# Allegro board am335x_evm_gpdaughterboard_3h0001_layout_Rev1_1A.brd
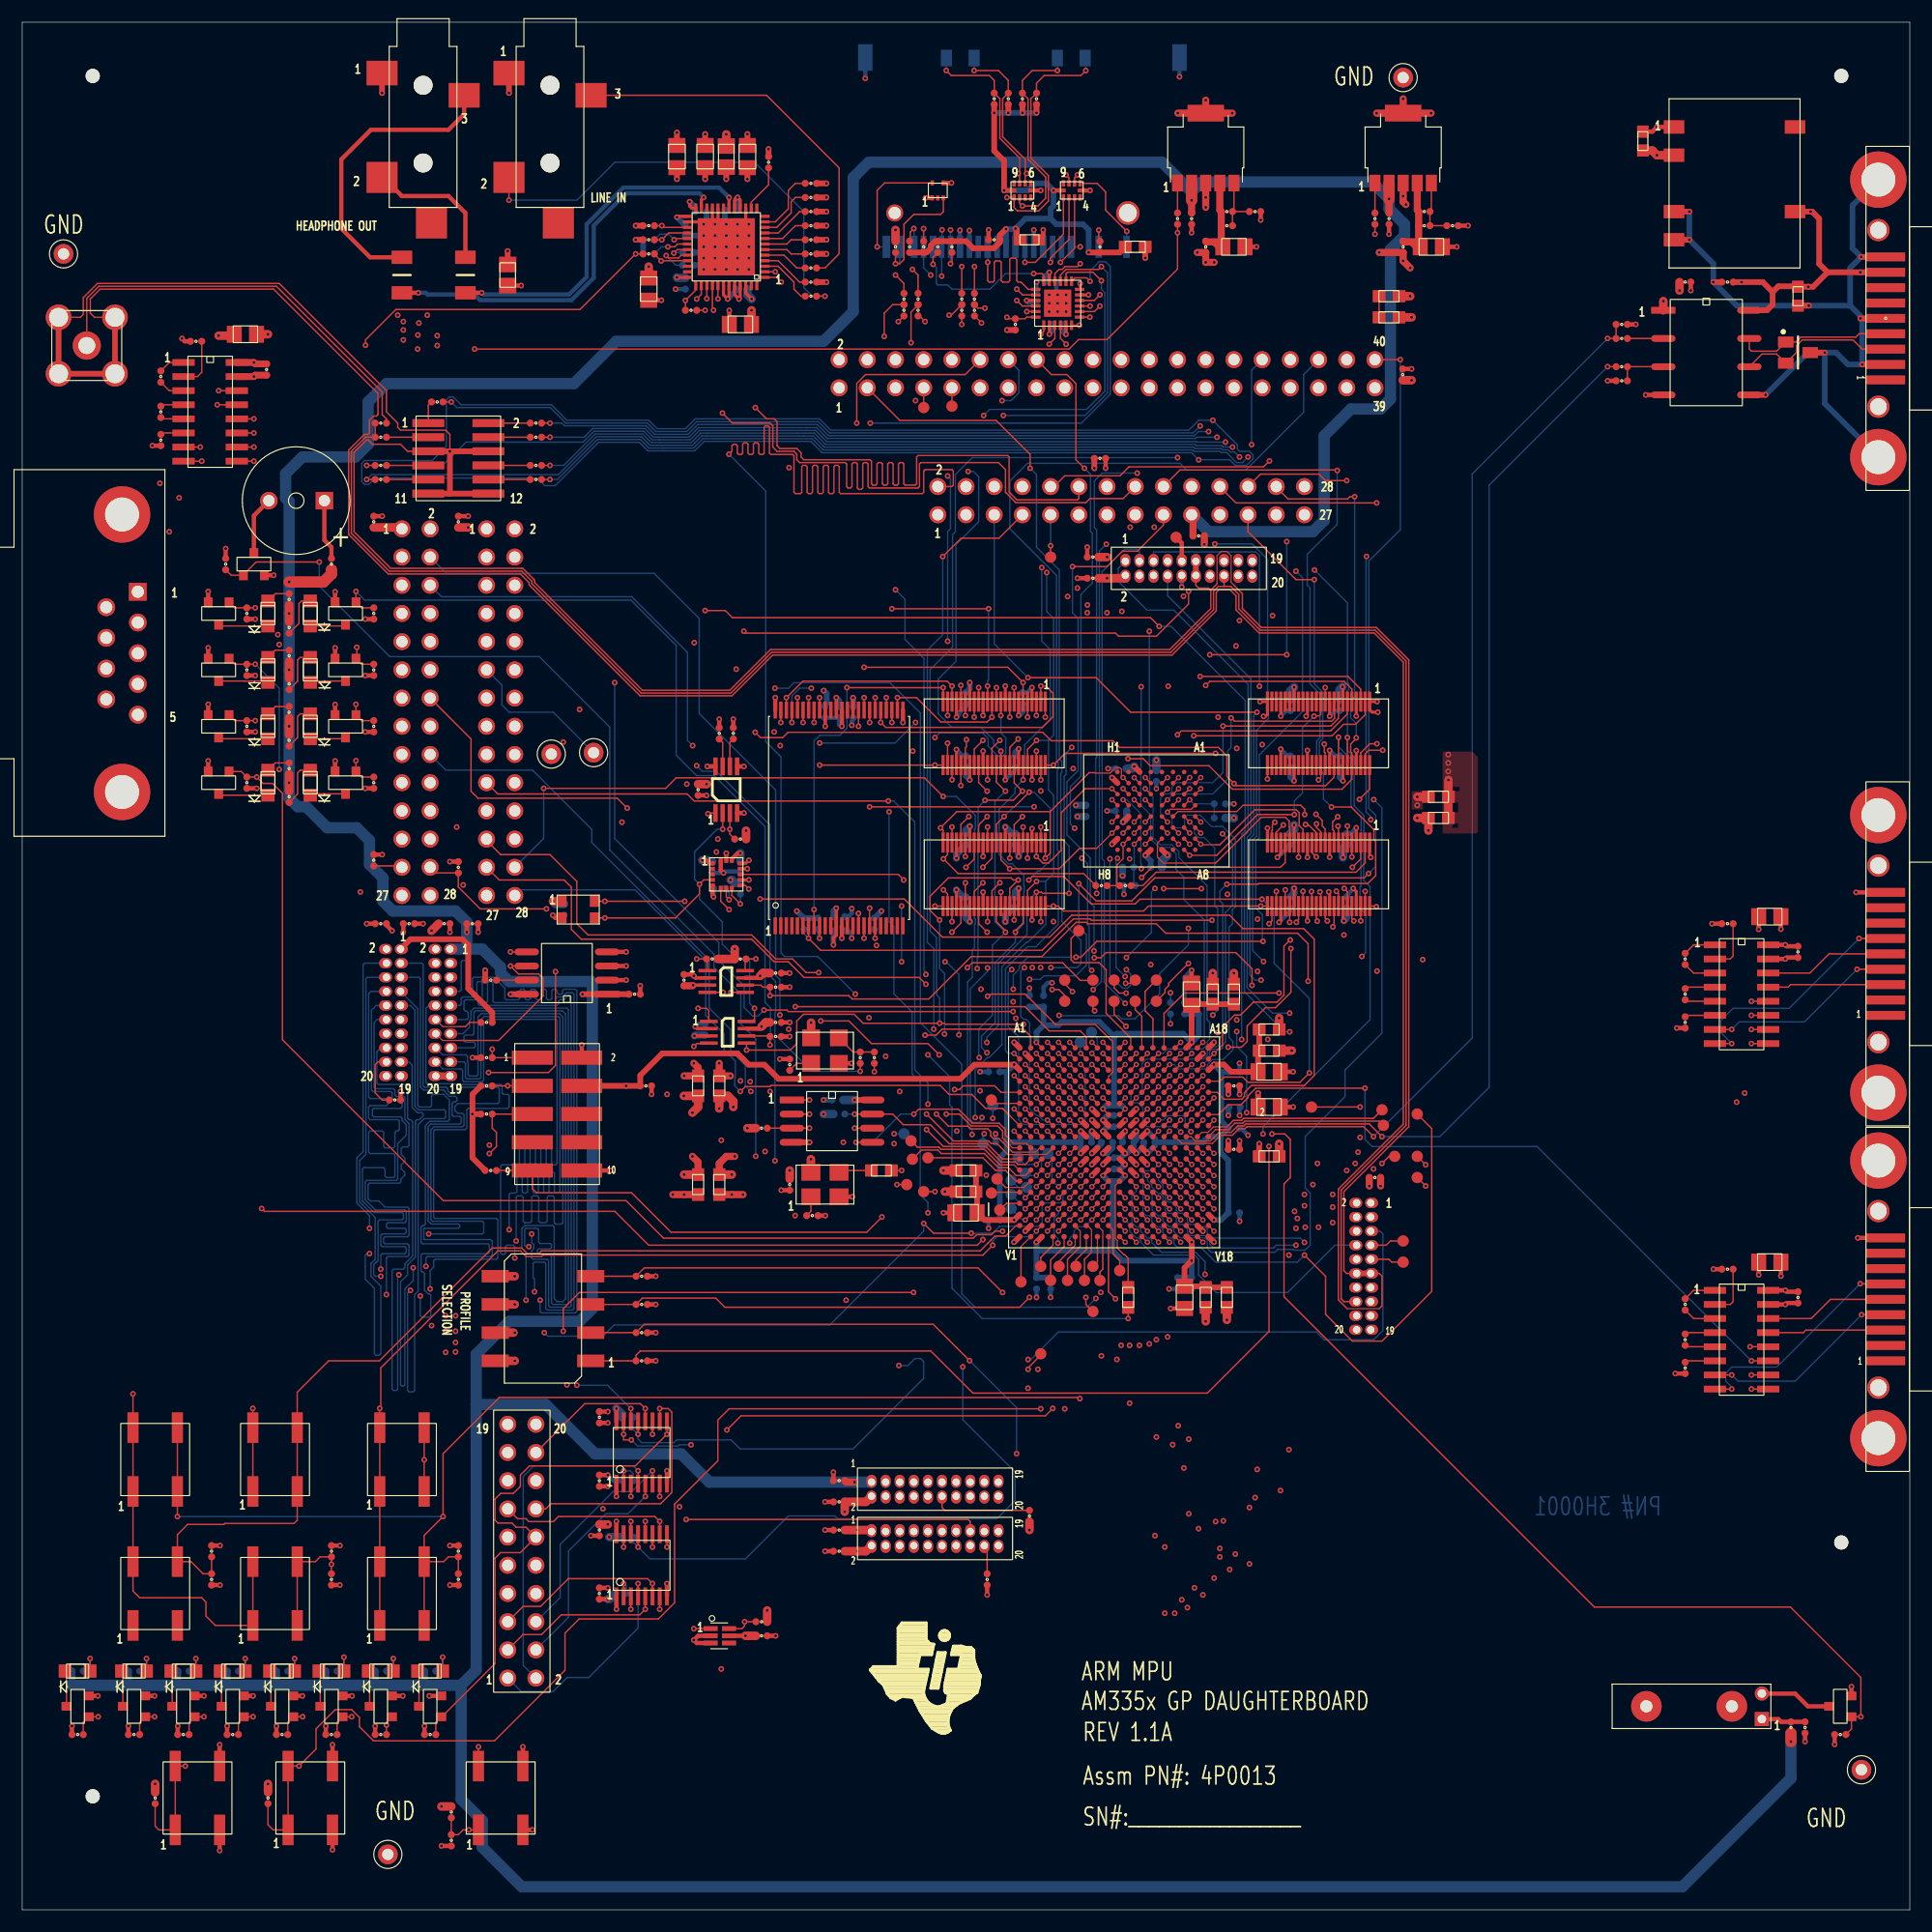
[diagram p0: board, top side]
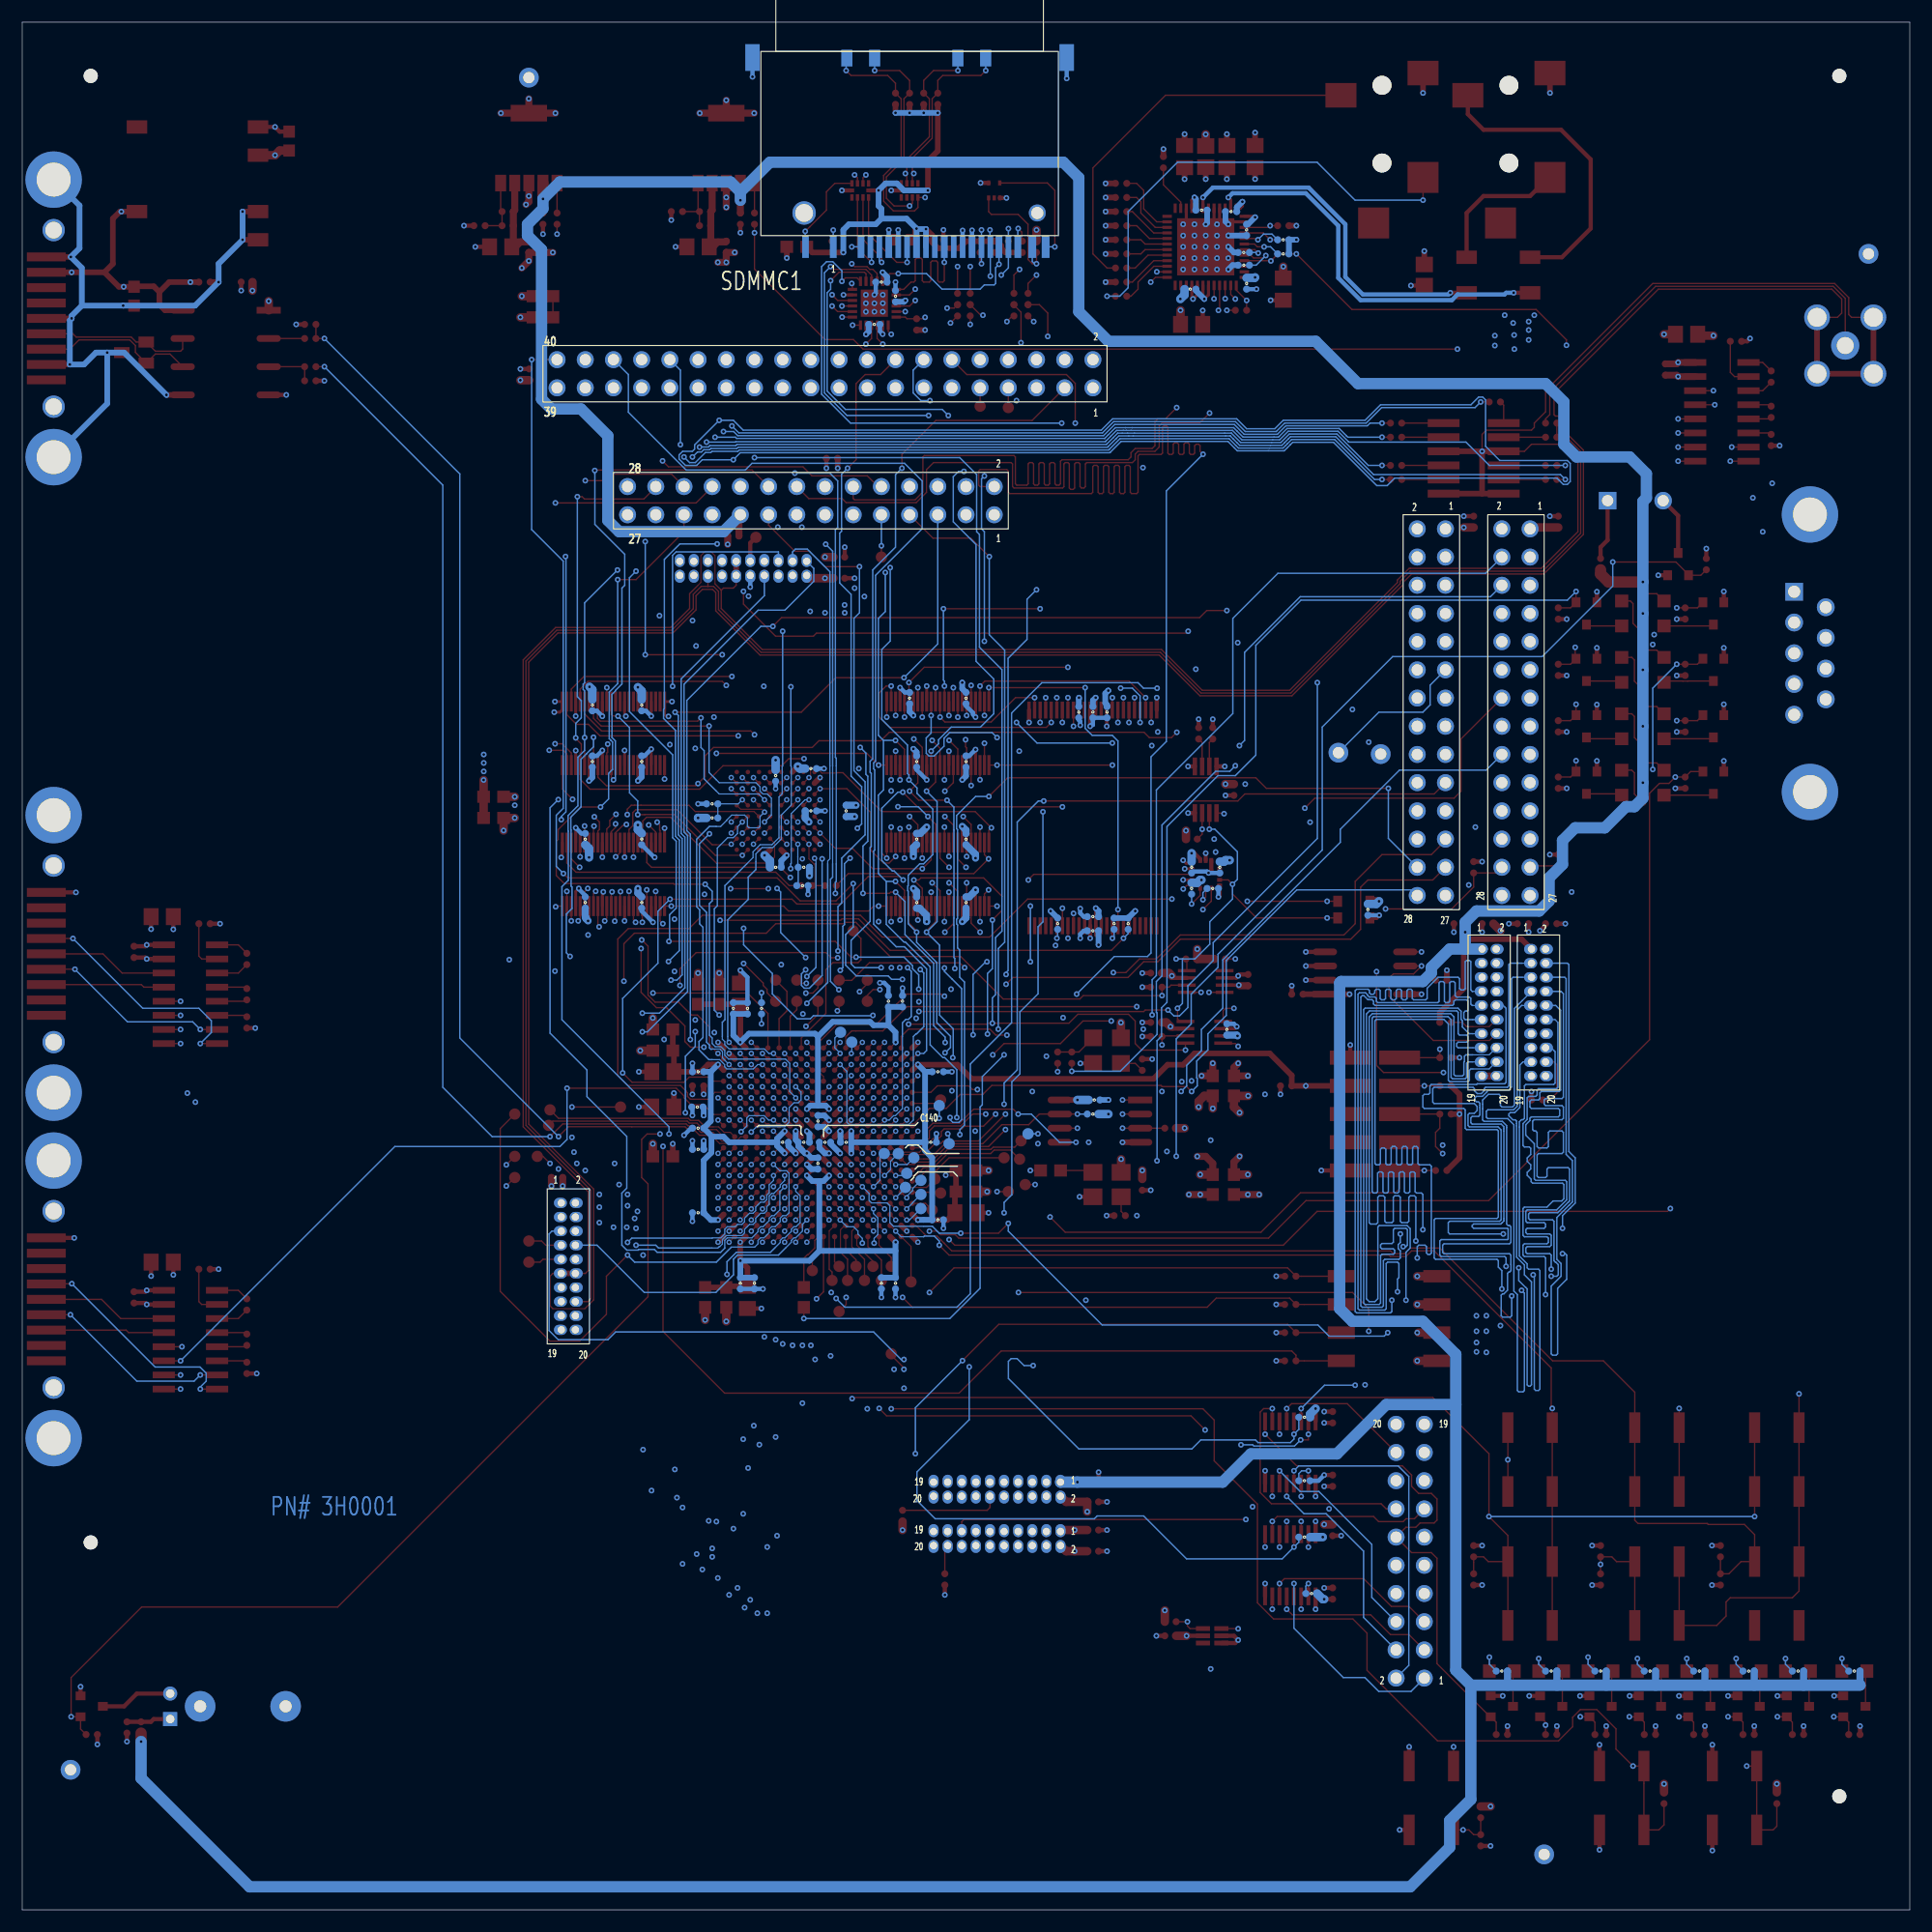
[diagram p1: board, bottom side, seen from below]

Outline 170 x 170 mm; copper layers: TOP, LY2_GND, LY3, LY4_PWR, LY5_PWR, LY6, LY7_GND, BOTTOM. Coordinates in mm from the lower left corner of the outline.
Outline path: 0,170 0,0 170,0 170,170 0,170

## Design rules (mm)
net group GROUP_3: nets AM335X_MDIO_CLK AM335X_MDIO_DATA
net group GROUP_2: nets AM335X_GPMC_A0 AM335X_GPMC_A4 AM335X_GPMC_A5 AM335X_GPMC_A6 AM335X_GPMC_A7 AM335X_GPMC_A8 AM335X_GPMC_A9 AM335X_GPMC_A10 AM335X_GPMC_A11 AM335X_GPMC_WPN
net group GROUP_6: nets AM335X_GPMC_A1 AM335X_GPMC_A2 AM335X_GPMC_A3
net group GROUP_21: nets AM335X_GPMC_AD4 AM335X_GPMC_AD5 AM335X_GPMC_AD6 AM335X_GPMC_AD7
net group GROUP_29: nets MON_AIN0 MON_AIN1 MON_AIN2 MON_AIN3 MON_AIN4 MON_AIN5 MON_AIN6 MON_AIN7 TSC_AIN0 TSC_AIN1 TSC_AIN2 TSC_AIN3 TSC_AIN4 TSC_AIN5 TSC_AIN6 TSC_AIN7
net group GROUP_31: nets GPMC_AD8 GPMC_AD9 GPMC_AD10 GPMC_AD11 GPMC_AD12 GPMC_AD13 GPMC_AD14 GPMC_AD15 LCD_DATA0 LCD_DATA1 LCD_DATA2 LCD_DATA3 LCD_DATA4 LCD_DATA5 LCD_DATA6 LCD_DATA7 LCD_DATA8 LCD_DATA9 LCD_DATA10 LCD_DATA11 LCD_DATA12 LCD_DATA13 LCD_DATA14 LCD_DATA15 LCD_DEN LCD_HSYNC LCD_PCLK LCD_VSYNC LCDBD_D0 LCDBD_D1 LCDBD_D2 LCDBD_D3 LCDBD_D4 LCDBD_D5 LCDBD_D6 LCDBD_D7 LCDBD_D8 LCDBD_D9 LCDBD_D10 LCDBD_D11 LCDBD_D12 LCDBD_D13 LCDBD_D14 LCDBD_D15 LCDBD_D16 LCDBD_D17 LCDBD_D18 LCDBD_D19 LCDBD_D20 LCDBD_D21 LCDBD_D22 LCDBD_D23 LCDBD_DEN LCDBD_HSYNC LCDBD_PCLK LCDBD_VSYNC
net group GROUP_34: nets VCPLD_VIO1 VCPLD_VIO2 VCPLD_VIO3 VCPLD_VIO4
net group GROUP_38: nets AUD_HPLOUT AUD_HPLOUT_JCK AUD_HPROUT AUD_HPROUT_JCK
net group POWER_TRACE: nets VDDSHV5 VGP_1_8D VGP_3_3D
net group SD_MMC_CC: nets SDMMC1_CLK SDMMC1_CMD SDMMC1_DAT0 SDMMC1_DAT1 SDMMC1_DAT2 SDMMC1_DAT3 SDMMC1_DAT4 SDMMC1_DAT5 SDMMC1_DAT6 SDMMC1_DAT7
nets with their own width: min track width 0.381; nets DGND V3_3D VSDMMC1
nets with their own width: min track width 0.508; nets GND_CAN0 VCAN0 VCPLD_INT VDDSHV1 VDDSHV2 VDDSHV3
nets with their own width: min track width 0.635; nets VDDSHV6
nets with their own width: min track width 0.762; nets V1_8D V5_0D

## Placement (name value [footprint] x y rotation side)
C1  0.01uF  [SM-7351-CAP-0402]  55.16 82.46 0 top
C2  0.1uF  [SM-7351-CAP-0402]  39.28 125.01 90 top
C3  0.1uF  [SM-7351-CAP-0402]  31.66 125.01 90 top
C4  0.1uF  [SM-7351-CAP-0402]  96.43 121.83 180 top
C5  0.1uF  [SM-7351-CAP-0402]  124.33 138.27 90 top
C6  0.1uF  [SM-7351-CAP-0402]  105.96 123.74 0 top
C7  0.1uF  [SM-7351-CAP-0402]  97.07 130.72 0 top
C8  0.01uF  [SM-7351-CAP-0402]  34.84 88.81 0 top
C9  0.01uF  [SM-7351-CAP-0402]  32.3 88.81 180 top
C10  0.01uF  [SM-7351-CAP-0402]  38.01 88.81 0 top
C11  0.01uF  [SM-7351-CAP-0402]  40.55 88.81 0 top
C12  0.01uF  [SM-7351-CAP-0402]  121.83 65.95 0 top
C13  0.01uF  [SM-7351-CAP-0402]  114.21 90.72 270 bottom
C14  0.01uF  [SM-7351-CAP-0402]  119.29 90.72 90 bottom
C15  0.01uF  [SM-7351-CAP-0402]  114.21 96.43 270 bottom
C16  0.01uF  [SM-7351-CAP-0402]  119.29 96.43 90 bottom
C17  0.01uF  [SM-7351-CAP-0402]  98.97 102.78 180 bottom
C18  0.01uF  [SM-7351-CAP-0402]  95.8 98.97 90 bottom
C19  0.01uF  [SM-7351-CAP-0402]  98.97 98.97 180 bottom
C20  1uF  [SM-7351-CAP-0402]  102.15 93.89 180 bottom
C21  0.1uF  [SM-7351-CAP-0402]  73.57 89.45 0 bottom
C22  0.01uF  [SM-7351-CAP-0402]  73.57 88.18 0 bottom
C23  0.01uF  [SM-7351-CAP-0402]  74.84 107.86 270 bottom
C24  0.01uF  [SM-7351-CAP-0402]  72.3 107.86 270 bottom
C25  0.1uF  [SM-7351-CAP-0402]  73.57 107.86 270 bottom
C26  0.01uF  [SM-7351-CAP-0402]  114.21 103.42 90 bottom
C27  0.01uF  [SM-7351-CAP-0402]  114.21 108.5 270 bottom
C28  0.01uF  [SM-7351-CAP-0402]  118.66 103.42 90 bottom
C29  0.01uF  [SM-7351-CAP-0402]  118.66 108.5 270 bottom
C30  0.01uF  [SM-7351-CAP-0402]  85 90.72 90 bottom
C31  0.01uF  [SM-7351-CAP-0402]  89.45 90.72 270 bottom
C32  0.01uF  [SM-7351-CAP-0402]  85 96.43 270 bottom
C33  0.01uF  [SM-7351-CAP-0402]  89.45 96.43 90 bottom
C34  0.01uF  [SM-7351-CAP-0402]  73.44 72.94 180 bottom
C35  0.01uF  [SM-7351-CAP-0402]  85 103.42 90 bottom
C36  0.01uF  [SM-7351-CAP-0402]  89.45 103.42 270 bottom
C37  0.01uF  [SM-7351-CAP-0402]  85 109.13 270 bottom
C38  0.01uF  [SM-7351-CAP-0402]  90.08 109.13 90 bottom
C39  0.01uF  [SM-7351-CAP-0402]  67.86 84.37 0 top
C40  0.01uF  [SM-7351-CAP-0402]  59.6 83.73 90 top
C41  0.01uF  [SM-7351-CAP-0402]  64.68 93.89 270 bottom
C42  0.01uF  [SM-7351-CAP-0402]  62.14 93.89 270 bottom
C43  0.01uF  [SM-7351-CAP-0402]  67.86 79.92 0 top
C44  0.01uF  [SM-7351-CAP-0402]  61.51 79.29 90 bottom
C45  0.01uF  [SM-7351-CAP-0402]  48.81 90.08 270 bottom
C46  0.01uF  [SM-7351-CAP-0402]  60.87 100.88 270 top
C47  0.01uF  [SM-7351-CAP-0402]  22.01 138.72 270 top
C48  10uF  [SM-7351-CAP-0805]  20.1 141.9 0 top
C49  3.3uF  [SM-7351-CAP-0603]  145.96 159.3 90 top
C50  0.1uF  [SM-7351-CAP-0402]  12.48 138.09 270 top
C51  0.01uF  [SM-7351-CAP-0402]  149.77 146.6 0 top
C52  0.1uF  [SM-7351-CAP-0402]  153.58 146.6 180 top
C53  0.1uF  [SM-7351-CAP-0402]  15.66 141.26 180 top
C54  3.3uF  [SM-7351-CAP-0603]  159.93 145.33 270 top
C55  0.1uF  [SM-7351-CAP-0402]  12.48 134.91 270 top
C56  0.1uF  [SM-7351-CAP-0402]  12.48 132.37 270 top
C57  100pF25V10%  [SM-7351-CAP-0402]  144.06 142.79 0 top
C58  100pF25V10%  [SM-7351-CAP-0402]  144.06 137.71 180 top
C59  10uF  [SM-7351-CAP-0805]  157.39 58.33 180 top
C60  0.01uF  [SM-7351-CAP-0402]  159.93 55.16 270 top
C62  0.1uF  [SM-7351-CAP-0402]  149.77 54.52 270 top
C63  0.1uF  [SM-7351-CAP-0402]  153.58 57.7 180 top
C64  0.1uF  [SM-7351-CAP-0402]  149.77 51.35 270 top
C68  0.1uF  [SM-7351-CAP-0402]  149.77 48.81 270 top
C69  0.01uF  [SM-7351-CAP-0402]  159.93 86.27 270 top
C70  10uF  [SM-7351-CAP-0805]  157.39 89.45 180 top
C73  0.1uF  [SM-7351-CAP-0402]  149.77 85.64 270 top
C74  0.1uF  [SM-7351-CAP-0402]  153.58 88.81 180 top
C75  0.1uF  [SM-7351-CAP-0402]  149.77 82.46 270 top
C76  0.1uF  [SM-7351-CAP-0402]  149.77 79.92 270 top
C77  0.01uF  [SM-7351-CAP-0402]  91.35 145.33 90 bottom
C78  0.1uF  [SM-7351-CAP-0402]  87.54 150.41 180 top
C79  4.7uF  [SM-7351-CAP-0603]  90.72 150.41 0 top
C80  0.01uF  [SM-7351-CAP-0402]  93.26 142.79 180 bottom
C81  0.01uF  [SM-7351-CAP-0402]  92.62 146.6 0 bottom
C121  0.01uF  [SM-7351-CAP-0402]  51.98 38.65 90 top
C122  0.01uF  [SM-7351-CAP-0402]  51.98 28.49 90 top
C123  0.01uF  [SM-7351-CAP-0402]  51.98 44.36 90 top
C124  0.01uF  [SM-7351-CAP-0402]  51.98 34.2 270 top
C125  1uF  [SM-7351-CAP-0402]  27.85 29.76 270 top
C126  1uF  [SM-7351-CAP-0402]  39.28 29.76 270 top
C127  1uF  [SM-7351-CAP-0402]  17.06 29.76 270 top
C128  0.01uF  [SM-7351-CAP-0402]  66.59 24.68 0 top
C129  1uF  [SM-7351-CAP-0402]  160.57 16.42 270 top
C130  1uF  [SM-7351-CAP-0402]  38.65 6.26 270 top
C131  0.01uF  [SM-7351-CAP-0402]  73.57 34.2 180 top
C132  0.01uF  [SM-7351-CAP-0402]  73.57 32.3 180 top
C133  0.01uF  [SM-7351-CAP-0402]  73.57 36.74 180 top
C134  0.01uF  [SM-7351-CAP-0402]  73.57 38.65 180 top
C135  0.01uF  [SM-7351-CAP-0402]  96.43 119.93 180 top
C136  0.01uF  [SM-7351-CAP-0402]  69.13 65.32 270 top
C137  0.01uF  [SM-7351-CAP-0402]  56.17 74.21 0 top
C138  0.01uF  [SM-7351-CAP-0402]  98.34 71.03 90 bottom
C139  0.01uF  [SM-7351-CAP-0402]  98.34 67.22 270 bottom
C140  0.01uF  [SM-7351-CAP-0402]  97.7 69.13 0 bottom
C141  0.01uF  [SM-7351-CAP-0402]  99.61 69.13 180 bottom
C142  10uF  [SM-7351-CAP-0805]  112.31 72.3 0 top
C143  0.01uF  [SM-7351-CAP-0402]  109.13 74.21 0 top
C144  0.01uF  [SM-7351-CAP-0402]  109.13 68.49 0 bottom
C145  0.01uF  [SM-7351-CAP-0402]  109.13 68.49 0 top
C146  0.01uF  [SM-7351-CAP-0402]  109.19 72.3 0 bottom
C147  0.01uF  [SM-7351-CAP-0402]  90.72 81.83 90 bottom
C148  0.01uF  [SM-7351-CAP-0402]  104.69 81.19 90 bottom
C149  0.01uF  [SM-7351-CAP-0402]  91.99 81.83 90 bottom
C150  0.01uF  [SM-7351-CAP-0402]  105.96 81.19 90 bottom
C151  10uF  [SM-7351-CAP-0805]  105.32 82.46 90 top
C152  0.01uF  [SM-7351-CAP-0402]  109.13 75.48 0 bottom
C153  0.01uF  [SM-7351-CAP-0402]  109.13 62.78 0 bottom
C154  0.01uF  [SM-7351-CAP-0402]  109.13 70.4 0 bottom
C155  0.01uF  [SM-7351-CAP-0402]  101.51 69.13 180 bottom
C156  10uF  [SM-7351-CAP-0805]  112.31 75.48 0 top
C157  10uF  [SM-7351-CAP-0805]  85 62.78 180 top
C158  0.01uF  [SM-7351-CAP-0402]  87.54 75.48 180 bottom
C159  0.01uF  [SM-7351-CAP-0402]  88.18 69.13 180 bottom
C160  0.01uF  [SM-7351-CAP-0402]  95.8 69.13 0 bottom
C161  0.01uF  [SM-7351-CAP-0402]  87.54 62.14 180 bottom
C162  0.01uF  [SM-7351-CAP-0402]  105.32 56.43 270 bottom
C163  0.01uF  [SM-7351-CAP-0402]  104.05 56.43 270 bottom
C164  0.01uF  [SM-7351-CAP-0402]  92.62 56.43 270 bottom
C165  0.01uF  [SM-7351-CAP-0402]  91.35 56.43 270 bottom
C166  10uF  [SM-7351-CAP-0805]  104.69 55.16 270 top
C197  47uF  [SM-7351-CAP-1206]  34.2 147.23 270 top
C198  47uF  [SM-7351-CAP-1206]  39.92 147.23 270 top
C199  0.01uF  [SM-7351-CAP-0402]  56.43 149.14 180 bottom
C200  0.01uF  [SM-7351-CAP-0402]  56.43 150.41 180 bottom
C201  0.01uF  [SM-7351-CAP-0402]  59.98 148.12 0 bottom
C202  0.01uF  [SM-7351-CAP-0402]  59.98 149.26 0 bottom
C203  10uF  [SM-7351-CAP-0805]  65.32 157.9 90 top
C204  0.1uF  [SM-7351-CAP-0402]  59.73 151.29 270 bottom
C205  0.01uF  [SM-7351-CAP-0402]  71.03 150.41 0 top
C206  0.01uF  [SM-7351-CAP-0402]  71.03 155.49 0 top
C207  0.01uF  [SM-7351-CAP-0402]  67.22 157.39 90 top
C208  0.01uF  [SM-7351-CAP-0402]  71.03 151.68 0 top
C209  0.1uF  [SM-7351-CAP-0402]  71.03 145.33 0 top
C210  0.1uF  [SM-7351-CAP-0402]  71.03 146.6 0 top
C211  0.1uF  [SM-7351-CAP-0402]  71.03 147.87 0 top
C212  0.1uF  [SM-7351-CAP-0402]  71.03 149.14 0 top
C213  10uF  [SM-7351-CAP-0805]  61.51 157.9 90 top
C214  0.1uF  [SM-7351-CAP-0402]  63.79 153.07 180 bottom
C215  10uF  [SM-7351-CAP-0805]  58.97 157.9 90 top
C216  0.1uF  [SM-7351-CAP-0402]  61.12 152.95 0 bottom
C217  10uF  [SM-7351-CAP-0805]  64.68 142.79 180 top
C218  0.1uF  [SM-7351-CAP-0402]  64.81 145.96 180 bottom
C219  10uF  [SM-7351-CAP-0805]  56.43 145.96 270 top
C220  0.1uF  [SM-7351-CAP-0402]  59.73 146.47 270 bottom
C221  0.01uF  [SM-7351-CAP-0402]  71.03 154.22 0 top
C222  0.01uF  [SM-7351-CAP-0402]  71.03 152.95 0 top
C223  0.01uF  [SM-7351-CAP-0402]  56.43 150.41 180 top
C224  0.01uF  [SM-7351-CAP-0402]  56.43 151.68 180 top
C225  15pF  [SM-7351-CAP-0402]  126.28 151.68 0 top
C226  2.2uF  [SM-7351-CAP-0805]  126.91 149.77 0 top
C227  1uF  [SM-7351-CAP-0402]  123.1 152.31 270 top
C228  15pF  [SM-7351-CAP-0402]  108.5 151.68 0 top
C229  2.2uF  [SM-7351-CAP-0805]  109.13 149.77 0 top
C230  1uF  [SM-7351-CAP-0402]  105.32 152.31 270 top
D1  Green LED  [SM_LED_0805]  36.74 21.5 180 top
D2  Green LED  [SM_LED_0805]  32.3 21.5 180 top
D3  Green LED  [SM_LED_0805]  27.85 21.5 180 top
D4  Green LED  [SM_LED_0805]  23.41 21.5 180 top
D5  Green LED  [SM_LED_0805]  18.96 21.5 180 top
D6  Green LED  [SM_LED_0805]  14.52 21.5 180 top
D7  Green LED  [SM_LED_0805]  10.07 21.5 180 top
D8  Green LED  [SM_LED_0805]  4.99 21.5 180 top
D9  Green LED  [SM_LED_0805]  25.95 116.75 270 top
D10  Green LED  [SM_LED_0805]  25.95 111.67 270 top
D11  Green LED  [SM_LED_0805]  25.95 106.59 270 top
D12  Green LED  [SM_LED_0805]  25.95 101.51 270 top
D13  Green LED  [SM_LED_0805]  22.14 116.75 270 top
D14  Green LED  [SM_LED_0805]  22.14 111.67 270 top
D15  Green LED  [SM_LED_0805]  22.14 106.59 270 top
D16  Green LED  [SM_LED_0805]  22.14 101.51 270 top
FB8  150OHM800mA  [SM-7351-IND-0805]  43.73 147.23 270 top
FB9  150OHM800mA  [SM-7351-IND-0805]  63.41 157.9 270 top
J1  Header_14x2_Male  [JUMP2X14-6040-1]  34.2 124.37 90 bottom
J2  Header_14x2_Male  [JUMP2X14-6040-1]  41.82 124.37 90 bottom
J3  Header_20x2_Male  [JUMP2X20-6040-1]  73.57 137.07 180 bottom
J4  Header_14x2_Male  [JUMP2X14-6040-1]  82.46 125.64 180 bottom
J5  Header_10x2_Male  [HEADER_10X2_TH]  34.07 86.52 270 bottom
J6  Header_10x2_Male  [HEADER_10X2_TH]  38.52 86.52 270 bottom
J7  Header_10x2_Male  [HEADER_10X2_TH]  121.45 63.66 270 bottom
J8  -  [FTR-106-53-G-D-06]  34.2 128.18 270 top
J9  SMAVertical  [TECONN_221789]  5.81 140.88 90 top
J10  Conn_DB9M_TH  [NORCOMP_DB9M_TH]  10.41 118.66 90 top
J11  Conn_DB9M  [NORCOMP_DB9M_SMD]  167.83 143.33 270 top
J12  Conn_DB9M  [NORCOMP_DB9M_SMD]  167.83 54.98 270 top
J14  Conn_DB9M  [NORCOMP_DB9M_SMD]  167.83 86.09 270 top
J15  MHC-W21-601  [MHC-W21-601-LF]  90.08 149.77 0 bottom
J18  Header_10x2_Male  [JUMP2X10-6040-1]  43.73 20.87 270 top
J19  Header_10x2_Female  [HEADER_10X2_TH_LCD]  76.49 32.8 0 top
J20  Header_10x2_Female  [HEADER_10X2_TH_LCD]  76.49 37.25 0 top
J21  Header_10x2_Female  [HEADER_10X2_TH_LCD]  99.35 120.18 0 top
J22  Header5x2SMD  [MOL-015-91-0100]  48.17 71.67 270 top
J26  3.5mm SJ3524  [SJ3524SMT4PIN]  32.16 165.42 90 top
J27  3.5mm SJ3524  [SJ3524SMT4PIN]  43.59 165.42 90 top
NOREF  -  []  81.83 20.87 0 top
NOREF#2  -  []  0 170 0 top
NOREF#3  -  [unnamed#2]  163.83 165.16 270 top
NOREF#4  -  []  170 0 90 top
NOREF#5  -  [unnamed#2]  163.83 33.08 270 top
NOREF#6  -  [unnamed#2]  6.35 165.16 270 top
NOREF#7  -  [unnamed#2]  6.35 10.22 270 top
Q1  BSS138  [SOT23-3]  36.74 18.33 90 top
Q2  BSS138  [SOT23-3]  32.3 18.33 90 top
Q3  BSS138  [SOT23-3]  27.85 18.33 90 top
Q4  BSS138  [SOT23-3]  23.41 18.33 90 top
Q5  BSS138  [SOT23-3]  18.96 18.33 90 top
Q6  BSS138  [SOT23-3]  14.52 18.33 90 top
Q7  BSS138  [SOT23-3]  10.07 18.33 90 top
Q8  BSS138  [SOT23-3]  4.99 18.33 90 top
Q9  BSS138  [SOT23-3]  20.87 121.2 0 top
Q10  BSS138  [SOT23-3]  163.74 18.33 90 top
Q11  BSS138  [SOT23-3]  29.12 116.75 180 top
Q12  BSS138  [SOT23-3]  29.12 111.67 180 top
Q13  BSS138  [SOT23-3]  29.12 106.59 180 top
Q14  BSS138  [SOT23-3]  29.12 101.51 180 top
Q15  BSS138  [SOT23-3]  17.69 116.75 180 top
Q16  BSS138  [SOT23-3]  17.69 111.67 180 top
Q17  BSS138  [SOT23-3]  17.69 106.59 180 top
Q18  BSS138  [SOT23-3]  17.69 101.51 180 top
R1  10K  [SM-7351-RES-0402]  42.2 83.73 180 top
R2  0  [SM-7351-RES-0603]  62.78 65.32 270 top
R3  0  [SM-7351-RES-0603]  127.55 100.24 0 top
R4  0  [SM-7351-RES-0603]  123.1 145.33 180 top
R5  0  [SM-7351-RES-0603]  62.78 74.21 90 top
R6  0  [SM-7351-RES-0603]  60.87 65.32 270 top
R7  0  [SM-7351-RES-0603]  127.55 98.34 0 top
R8  0  [SM-7351-RES-0603]  123.1 143.42 180 top
R9  0  [SM-7351-RES-0603]  60.87 74.21 90 top
R10  100K  [SM-7351-RES-0402]  39.28 93.89 270 top
R11  100K  [SM-7351-RES-0402]  31.66 94.53 270 top
R12  10K  [SM-7351-RES-0402]  41.82 79.92 0 top
R13  10K  [SM-7351-RES-0402]  33.57 72.94 180 top
R14  10K  [SM-7351-RES-0402]  99.61 93.89 180 bottom
R15  10K  [SM-7351-RES-0402]  102.15 102.15 90 bottom
R16  10K  [SM-7351-RES-0402]  107.86 98.34 0 bottom
R17  10K  [SM-7351-RES-0402]  107.86 99.61 180 bottom
R18  10K  [SM-7351-RES-0402]  70.4 88.81 90 bottom
R19  10K  [SM-7351-RES-0402]  76.75 88.81 90 bottom
R20  10K  [SM-7351-RES-0402]  71.67 88.81 90 bottom
R21  10K  [SM-7351-RES-0402]  66.59 70.4 180 top
R22  10K  [SM-7351-RES-0402]  73.57 71.67 180 bottom
R23  2.2K  [SM-7351-RES-0402]  64.68 85.64 180 top
R24  2.2K  [SM-7351-RES-0402]  62.14 85.64 0 top
R25  0  [SM-7351-RES-0402]  64.68 91.99 90 bottom
R26  10K  [SM-7351-RES-0402]  67.86 83.1 180 top
R27  0  [SM-7351-RES-0402]  62.78 91.99 0 bottom
R30  10K  [SM-7351-RES-0402]  67.86 78.65 180 top
R31  10K  [SM-7351-RES-0402]  64.68 96.43 0 top
R32  0  [SM-7351-RES-0402]  62.78 105.96 270 top
R33  0  [SM-7351-RES-0402]  64.05 105.96 270 top
R34  0  [SM-7351-RES-0402]  37.38 135.8 0 top
R35  0  [SM-7351-RES-0402]  32.3 132.63 180 top
R36  0  [SM-7351-RES-0402]  46.27 133.9 180 top
R37  0  [SM-7351-RES-0402]  46.27 132.63 180 top
R38  0  [SM-7351-RES-0402]  32.3 130.09 180 top
R39  0  [SM-7351-RES-0402]  46.27 130.09 180 top
R40  0  [SM-7351-RES-0402]  32.3 128.82 180 top
R41  0  [SM-7351-RES-0402]  46.27 128.82 180 top
R42  0  [SM-7351-RES-0402]  32.3 133.9 180 top
R43  33  [SM-7351-RES-0402]  144.06 141.52 0 top
R44  33  [SM-7351-RES-0402]  144.06 138.98 0 top
R47  0  [SM-7351-RES-0603]  100.24 149.77 0 top
R48  10K  [SM-7351-RES-0402]  97.07 149.77 270 top
R49  10K  [SM-7351-RES-0402]  83.73 149.77 90 top
R50  10K  [SM-7351-RES-0402]  82.46 149.77 90 top
R51  10K  [SM-7351-RES-0402]  79.92 149.77 270 top
R52  10K  [SM-7351-RES-0402]  81.19 149.77 270 top
R53  10K  [SM-7351-RES-0402]  91.35 163.11 270 top
R54  10K  [SM-7351-RES-0402]  90.08 163.11 270 top
R55  10K  [SM-7351-RES-0402]  88.81 163.11 270 top
R56  10K  [SM-7351-RES-0402]  87.54 163.11 270 top
R57  470K  [SM-7351-RES-0402]  78.65 149.77 90 top
R100  10K  [SM-7351-RES-0402]  54.52 44.36 180 bottom
R101  10K  [SM-7351-RES-0402]  54.52 33.57 180 bottom
R102  0  [SM-7351-RES-0402]  53.89 28.49 180 bottom
R103  0  [SM-7351-RES-0402]  54.52 38.65 0 bottom
R104  150  [SM-7351-RES-0402]  36.74 21.5 180 bottom
R105  150  [SM-7351-RES-0402]  32.3 21.5 180 bottom
R106  150  [SM-7351-RES-0402]  27.85 21.5 180 bottom
R107  150  [SM-7351-RES-0402]  23.41 21.5 180 bottom
R108  150  [SM-7351-RES-0402]  18.96 21.5 180 bottom
R109  150  [SM-7351-RES-0402]  14.52 21.5 180 bottom
R110  150  [SM-7351-RES-0402]  10.07 21.5 180 bottom
R111  150  [SM-7351-RES-0402]  4.99 21.5 180 bottom
R112  100K  [SM-7351-RES-0402]  36.74 15.79 0 top
R113  100K  [SM-7351-RES-0402]  18.96 15.79 0 top
R114  100K  [SM-7351-RES-0402]  32.3 15.79 0 top
R115  100K  [SM-7351-RES-0402]  27.85 15.79 0 top
R116  100K  [SM-7351-RES-0402]  23.41 15.79 0 top
R117  100K  [SM-7351-RES-0402]  14.52 15.79 0 top
R118  100K  [SM-7351-RES-0402]  10.07 15.79 0 top
R119  100K  [SM-7351-RES-0402]  4.99 15.79 0 top
R120  33  [SM-7351-RES-0402]  27.85 121.2 270 top
R121  2.2K  [SM-7351-RES-0402]  27.85 32.3 270 top
R122  2.2K  [SM-7351-RES-0402]  39.28 32.3 270 top
R123  2.2K  [SM-7351-RES-0402]  17.06 32.3 270 top
R124  2.2K  [SM-7351-RES-0402]  18.33 121.2 270 top
R125  62.5  [SM-7351-RES-0402]  159.3 16.42 270 top
R126  10K  [SM-7351-RES-0402]  66.59 25.95 0 top
R127  10K  [SM-7351-RES-0402]  38.65 8.8 90 top
R128  2.2K  [SM-7351-RES-0402]  163.74 15.79 0 top
R129  150  [SM-7351-RES-0402]  24.04 115.48 90 top
R130  150  [SM-7351-RES-0402]  24.04 110.4 90 top
R131  150  [SM-7351-RES-0402]  24.04 105.32 90 top
R132  150  [SM-7351-RES-0402]  24.04 100.24 90 top
R133  150  [SM-7351-RES-0402]  24.04 118.02 270 top
R134  150  [SM-7351-RES-0402]  24.04 112.94 270 top
R135  150  [SM-7351-RES-0402]  24.04 107.86 270 top
R136  150  [SM-7351-RES-0402]  24.04 102.78 270 top
R137  100K  [SM-7351-RES-0402]  31.66 116.75 90 top
R138  100K  [SM-7351-RES-0402]  20.23 116.75 90 top
R139  100K  [SM-7351-RES-0402]  31.66 111.67 90 top
R140  100K  [SM-7351-RES-0402]  31.66 106.59 90 top
R141  100K  [SM-7351-RES-0402]  31.66 101.51 90 top
R142  100K  [SM-7351-RES-0402]  20.23 111.67 90 top
R143  100K  [SM-7351-RES-0402]  20.23 106.59 90 top
R144  100K  [SM-7351-RES-0402]  20.23 101.51 90 top
R145  10K  [SM-7351-RES-0402]  90.72 35.47 270 top
R146  10K  [SM-7351-RES-0402]  86.91 29.76 90 top
R148  10K  [SM-7351-RES-0402]  55.79 57.06 180 top
R149  10K  [SM-7351-RES-0402]  55.79 54.52 180 top
R150  10K  [SM-7351-RES-0402]  55.79 51.98 180 top
R151  10K  [SM-7351-RES-0402]  55.79 49.44 180 top
R152  0  [SM-7351-RES-0402]  71.16 62.52 180 top
R153  1K  [SM-7351-RES-0402]  42.2 66.59 180 top
R154  1K  [SM-7351-RES-0402]  41.82 74.21 180 top
R155  1K  [SM-7351-RES-0402]  41.82 71.67 180 top
R156  0  [SM-7351-RES-0603]  99.61 55.16 270 top
R157  0  [SM-7351-RES-0603]  77.38 66.59 180 top
R158  0  [SM-7351-RES-0402]  103.42 81.19 270 bottom
R159  1K  [SM-7351-RES-0402]  41.82 76.75 0 top
R160  0  [SM-7351-RES-0603]  112.31 67.86 0 top
R161  0  [SM-7351-RES-0603]  85 66.59 180 top
R162  0  [SM-7351-RES-0603]  85 64.68 180 top
R163  0  [SM-7351-RES-0603]  109.13 82.46 90 top
R164  0  [SM-7351-RES-0603]  107.23 82.46 90 top
R165  0  [SM-7351-RES-0603]  112.31 77.38 0 top
R166  0  [SM-7351-RES-0603]  112.31 79.29 0 top
R167  0  [SM-7351-RES-0603]  108.5 55.16 270 top
R168  0  [SM-7351-RES-0603]  106.59 55.16 270 top
R229  0  [SM-7351-RES-0402]  69.13 76.11 270 top
R230  0  [SM-7351-RES-0402]  76.75 76.75 90 top
R231  0  [SM-7351-RES-0402]  75.48 76.75 90 top
R232  0  [SM-7351-RES-0402]  56.43 149.14 180 top
R233  0  [SM-7351-RES-0402]  60.24 144.06 0 top
R235  10K  [SM-7351-RES-0402]  22.14 10.07 90 top
R236  10K  [SM-7351-RES-0402]  11.98 10.07 90 top
R237  0  [SM-7351-RES-0402]  124.37 149.77 90 top
R238  0  [SM-7351-RES-0402]  121.83 152.31 270 top
R239  51K  [SM-7351-RES-0402]  126.28 152.95 180 top
R240  30.1K  [SM-7351-RES-0402]  128.82 151.68 180 top
R241  0  [SM-7351-RES-0402]  106.59 149.77 90 top
R242  0  [SM-7351-RES-0402]  104.05 152.31 270 top
R243  14K  [SM-7351-RES-0402]  108.5 152.95 180 top
R244  30.1K  [SM-7351-RES-0402]  111.04 152.95 180 top
R247  10K  [SM-7351-RES-0402]  89.45 142.79 270 top
R249  0  [SM-7351-RES-0402]  97.19 92.24 0 top
R250  0  [SM-7351-RES-0402]  99.35 92.24 180 top
R251  0  [SM-7351-RES-0402]  84.62 145.07 270 top
R252  0  [SM-7351-RES-0402]  85.76 145.07 270 top
R253  0  [SM-7351-RES-0402]  79.41 145.07 270 top
R254  0  [SM-7351-RES-0402]  80.68 145.07 270 top
R255  0  [SM-7351-RES-0402]  84.62 144.06 90 top
R256  0  [SM-7351-RES-0402]  79.41 144.06 90 top
R257  0  [SM-7351-RES-0402]  85.76 144.06 90 top
R258  0  [SM-7351-RES-0402]  80.68 144.06 90 top
R259  0  [SM-7351-RES-0402]  99.73 92.24 0 bottom
SPKR1  AudioBuzzer_AI_1027  [SPKR_AI_1027]  27.22 126.91 180 top
SW1  B3SL  [SW_B3SL-1022P]  34.2 40.55 270 top
SW2  B3SL  [SW_B3SL-1022P]  34.2 28.49 270 top
SW3  B3SL  [SW_B3SL-1022P]  22.77 40.55 270 top
SW4  B3SL  [SW_B3SL-1022P]  22.77 28.49 270 top
SW5  B3SL  [SW_B3SL-1022P]  11.98 40.55 270 top
SW6  B3SL  [SW_B3SL-1022P]  11.98 28.49 270 top
SW7  B3SL  [SW_B3SL-1022P]  43.09 10.07 270 top
SW8  Switch4pos  [219-4MST]  46.9 53.25 180 top
SW9  B3SL  [SW_B3SL-1022P]  25.95 10.07 270 top
SW10  B3SL  [SW_B3SL-1022P]  15.79 10.07 270 top
TP1  TP  [TH_TP_5002]  47.65 104.09 0 top
TP2  TP  [TH_TP_5002]  51.46 104.21 0 top
TP3  TP1mm  [TP_SMD1MMCIRCLE]  92.62 121.83 0 top
TP4  TP1mm  [TP_SMD1MMCIRCLE]  124.37 60.24 0 top
TP5  TP1mm  [TP_SMD1MMCIRCLE]  124.37 58.33 0 top
TP13  TP1mm  [TP_SMD1MMCIRCLE]  103.92 123.61 0 top
TP14  TP1mm  [TP_SMD1MMCIRCLE]  91.73 50.08 0 top
TP15  TP1mm  [TP_SMD1MMCIRCLE]  95.16 88.18 0 top
TP16  TP1mm  [TP_SMD1MMCIRCLE]  102.15 81.83 0 top
TP17  TP1mm  [TP_SMD1MMCIRCLE]  98.34 81.83 0 top
TP18  TP1mm  [TP_SMD1MMCIRCLE]  98.34 83.73 0 top
TP19  TP1mm  [TP_SMD1MMCIRCLE]  100.24 83.73 0 top
TP20  TP1mm  [TP_SMD1MMCIRCLE]  100.24 81.83 0 top
TP21  TP1mm  [TP_SMD1MMCIRCLE]  93.89 81.83 0 top
TP22  TP1mm  [TP_SMD1MMCIRCLE]  102.15 83.73 0 top
TP23  TP1mm  [TP_SMD1MMCIRCLE]  93.89 83.73 0 top
TP24  TP1mm  [TP_SMD1MMCIRCLE]  96.43 83.73 0 top
TP25  TP1mm  [TP_SMD1MMCIRCLE]  96.43 81.83 0 top
TP27  TP1mm  [TP_SMD1MMCIRCLE]  125.64 71.67 0 top
TP28  TP1mm  [TP_SMD1MMCIRCLE]  125.64 65.95 0 top
TP29  TP1mm  [TP_SMD1MMCIRCLE]  125.64 67.86 0 top
TP31  TP1mm  [TP_SMD1MMCIRCLE]  87.41 72.43 180 bottom
TP32  TP1mm  [TP_SMD1MMCIRCLE]  96.43 53.89 0 top
TP33  TP1mm  [TP_SMD1MMCIRCLE]  116.12 72.3 0 top
TP34  TP1mm  [TP_SMD1MMCIRCLE]  90.46 65.06 180 bottom
TP35  TP1mm  [TP_SMD1MMCIRCLE]  87.29 72.94 0 top
TP38  TP  [TH_TP_5002]  32.93 4.99 0 top
TP39  TP  [TH_TP_5002]  3.72 149.14 0 top
TP40  TP  [TH_TP_5002]  124.37 165.01 0 top
TP41  TP  [TH_TP_5002]  165.65 12.61 0 top
TP42  TP1mm  [TP_SMD1MMCIRCLE]  123.61 67.86 0 top
TP43  TP1mm  [TP_SMD1MMCIRCLE]  81.19 64.68 0 top
TP44  TP1mm  [TP_SMD1MMCIRCLE]  122.47 72.05 0 top
TP45  TP1mm  [TP_SMD1MMCIRCLE]  122.59 70.65 0 top
TP46  TP1mm  [TP_SMD1MMCIRCLE]  94.14 56.68 0 top
TP47  TP1mm  [TP_SMD1MMCIRCLE]  95.67 56.68 0 top
TP48  TP1mm  [TP_SMD1MMCIRCLE]  97.07 56.68 0 top
TP49  TP1mm  [TP_SMD1MMCIRCLE]  98.84 57.57 0 top
TP50  TP1mm  [TP_SMD1MMCIRCLE]  89.95 56.55 0 top
TP51  TP1mm  [TP_SMD1MMCIRCLE]  91.73 57.95 0 top
TP52  TP1mm  [TP_SMD1MMCIRCLE]  92.62 56.68 0 top
TP53  TP1mm  [TP_SMD1MMCIRCLE]  93.38 57.95 0 top
TP54  TP1mm  [TP_SMD1MMCIRCLE]  94.91 57.95 0 top
TP55  TP1mm  [TP_SMD1MMCIRCLE]  96.43 57.95 0 top
TP56  TP1mm  [TP_SMD1MMCIRCLE]  86.52 69 180 bottom
TP57  TP1mm  [TP_SMD1MMCIRCLE]  79.41 69.89 180 bottom
TP64  TP1mm  [TP_SMD1MMCIRCLE]  89.7 67.73 180 bottom
TP65  TP1mm  [TP_SMD1MMCIRCLE]  80.05 69.25 0 top
TP66  TP1mm  [TP_SMD1MMCIRCLE]  80.17 67.6 0 top
TP67  TP1mm  [TP_SMD1MMCIRCLE]  90.33 66.33 180 bottom
TP68  TP1mm  [TP_SMD1MMCIRCLE]  81.57 67.73 0 top
TP69  TP1mm  [TP_SMD1MMCIRCLE]  87.79 65.82 0 top
TP70  TP1mm  [TP_SMD1MMCIRCLE]  79.67 65.32 0 top
TP71  TP1mm  [TP_SMD1MMCIRCLE]  92.37 68.11 180 bottom
TP72  TP1mm  [TP_SMD1MMCIRCLE]  87.29 64.55 0 top
TP73  TP1mm  [TP_SMD1MMCIRCLE]  89.06 65.7 180 bottom
TP74  TP1mm  [TP_SMD1MMCIRCLE]  88.05 63.03 0 top
TP75  TP1mm  [TP_SMD1MMCIRCLE]  89.06 64.43 180 bottom
TP76  TP1mm  [TP_SMD1MMCIRCLE]  89.06 63.16 180 bottom
TP77  TP1mm  [TP_SMD1MMCIRCLE]  91.1 68.11 180 bottom
TP78  TP1mm  [TP_SMD1MMCIRCLE]  81.19 135.29 0 top
TP79  TP1mm  [TP_SMD1MMCIRCLE]  83.73 135.42 0 top
TP80  TP1mm  [TP_SMD1MMCIRCLE]  95.29 78.14 180 bottom
TP81  TP1mm  [TP_SMD1MMCIRCLE]  96.3 79.03 180 bottom
U1  CAT24C256W  [SOIC_8]  49.06 84.37 90 top
U2  SN74LVC16T245  [TVSOP-DGV]  116.75 93.26 270 top
U3  M29W128G  [TBGA64]  102.15 98.97 270 top
U4  SN74LVC16T245  [TVSOP-DGV]  116.75 105.96 270 top
U5  MT29F2G08AB  [SKT-TSOP48SM]  73.57 98.34 90 top
U6  SN74LVC16T245  [TVSOP-DGV]  87.54 93.26 270 top
U7  SN74LVC16T245  [TVSOP-DGV]  87.54 105.96 270 top
U8  W25Q64  [SOIC_8]  72.94 71.03 270 top
U9  LIS331DLH  [LGA16PIN_3X3]  63.41 93.26 0 top
U10  TXS0102  [DCT8]  63.41 83.6 0 top
U11  TXS0102  [DCT8]  63.54 79.03 0 top
U12  TSL2550  [T_SMD-4]  50.08 90.08 0 top
U13  TMP275  [MSOP_DGK]  63.41 100.88 90 top
U14  RSZ-3.305HP  [RSZ]  154.22 155.49 0 top
U15  MAX3232E  [U_16_D]  16.93 134.91 270 top
U16  ISO1050  [SO8_W_DUB]  151.68 142.15 270 top
U17  PSM712  [SM-SOT-23]  159.93 140.25 180 top
U19  MAX3232E  [U_16_D]  154.85 51.35 270 top
U22  MAX3232E  [U_16_D]  154.85 82.46 270 top
U23  TXS02612  [U_24_RTW]  93.26 144.69 90 top
U25  TPD6E001  [U_10_RSE]  94.53 154.85 0 top
U26  TPD6E001  [U_10_RSE]  90.08 154.85 0 top
U27  TPD2E001  [U_5_DRL]  82.46 154.85 0 top
U39  TCA6408A  [U_16_PW]  55.79 41.19 0 top
U40  TCA6408A  [U_16_PW]  55.79 31.03 0 top
U41  PicoHaptics 304-100  [PICO_304-100]  151.68 18.33 270 top
U42  SN74LVC2G07  [U_6_DCK]  62.78 24.68 90 top
U43  EPM2210  [FBGA324]  98.34 69.13 0 top
U51  TLV320AIC3106  [VQFN48_RGZ]  63.41 149.77 180 top
U52  TPS79501  [SOT223_6PIN]  124.37 158.66 0 top
U53  TPS79501  [SOT223_6PIN]  106.59 158.66 0 top
Y2  25MHz  [ASF_SMD3_2X5MM]  72.3 65.32 90 top
Y5  12MHz  [ECS_SMD3_2X5MM]  72.3 77.38 90 top

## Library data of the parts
C1 C8-C19 C22-C24 C26-C47 C51 C60 C69 C77 C80 C81 C121-C124 C128 C131-C141 C143-C150 C152-C155 C158-C165 C199-C202 C205-C208 C221-C224 = 0.01uFCapacitor16V10%0402: Tolerance: TOLERANCE; User Part Number: USERPART#
C2-C7 C21 C25 C50 C52 C53 C55 C56 C62-C64 C68 C73-C76 C78 C204 C209-C212 C214 C216 C218 C220 = 0.1uFCapacitor16V10%0402: Tolerance: TOLERANCE; User Part Number: USERPART#
C20 C125-C127 C129 C130 C227 C230 = 1uFCapacitor10V10%0402: Tolerance: TOLERANCE; User Part Number: USERPART#
C48 C59 C70 C142 C151 C156 C157 C166 C203 C213 C215 C217 C219 = 10uFCapacitor16V10%0805
C49 C54 = 3.3uFCapacitor16V10%0603
C57 C58 = 100pFCapacitor16V10%0402: Tolerance: TOLERANCE; User Part Number: USERPART#
C79 = 4.7uFCapacitor6.3V20%smdX5R0603
C197 C198 = 47uFCapacitor16V20%1206
C225 C228 = 15pFCapacitor50V10%smd0402: Tolerance: TOLERANCE; User Part Number: USERPART#
C226 C229 = 2.2uF16V10%SMD0805
D1-D16 = LED_Green
FB8 FB9 = FerBead_180ohm200mA
J1 J2 J4 = Header_28pin_0.1in_Male
J3 = Header_40pin_0.1in_Male
J5-J7 = Header10x2_0.05inpitch_male
J8 = Header6x2FTR
J9 = Conn_SMA_Female
J10 = Conn_DSUB9M_TH
J11 J12 J14 = Conn_DSUB9M
J15 = Conn_SDCard_MHC-W21-601
J18 = Header_20pin_0.1in_Male
J19-J21 = Header10x2_0.5in_f_rowswap
J22 = Header5x2SMD
J26 J27 = Conn_3.5mm_SJ3524SMT
Q1-Q18 = MOSFET_NChan_BSS138
R1 R12-R22 R26 R30 R31 R48-R56 R100 R101 R126 R127 R145 R146 R148-R151 R235 R236 R247 = 10KOhmResistor1/16W0402
R2-R9 R47 R156 R157 R160-R168 = ZeroOhmResistor1/16W0603
R10 R11 R112-R119 R137-R144 = 100KOhmResistor1/16W0402
R23 R24 R121-R124 R128 = 2.2KOhmResistor1/16W0402
R25 R27 R32-R42 R102 R103 R152 R158 R229-R233 R237 R238 R241 R242 R249-R259 = ZeroOhmResistor1/16W0402
R43 R44 R120 = 33ohmResistor1/16W5%0402
R57 = 470Kohm1/16W1%SMD0402
R104-R111 R129-R136 = 150ohm1/16W1%SMD0402
R125 = 62.5OhmResistor1/16W0402
R153-R155 R159 = 1KOhmResistor1/16W0402
R239 = 51Kohm1/16W1%smd0402
R240 R244 = 30.1Kohm1/16W1%smd0402
R243 = 14KOhmResistor1/16W0402
SPKR1 = AudioBuzzer_AI_1027
SW1-SW7 SW9 SW10 = Switch_Pushbuttonsmd
SW8 = SwitchDIP4pos_smd
TP1 TP2 TP38-TP41 = TestPointThroughHole
TP3-TP5 TP13-TP25 TP27-TP29 TP31-TP35 TP42-TP57 TP64-TP81 = Testpoint_SMD1mmCircle
U1 = CAT24C256W
U2 U4 U6 U7 = SN74LVC16T245DGV
U3 = M29W128G
U5 = MT29F2G08ABBE
U8 = W25Q64
U9 = LIS331DLH
U10 U11 = TXS0102
U12 = TSL2550
U13 = TMP275
U14 = IsoReg5V_RSZ-3.305HP
U15 U19 U22 = MAX3232E
U16 = ISO1050
U17 = PSM712
U23 = TXS02612
U25 U26 = TPD6E001RSE
U27 = TPD2E001DRL
U39 U40 = TCA6408A
U41 = Haptics_Pico_304-100
U42 = SN74LVC2G07
U43 = EPM2210F324
U51 = TLV320AIC3106
U52 U53 = TPS79501
Y2 = Oscillator25MHzSMD
Y5 = Oscillator_12MHz

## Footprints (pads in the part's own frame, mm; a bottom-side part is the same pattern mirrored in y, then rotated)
219-4MST
  rect 2.438x1.118 smd: 1(-4.3,3.81) 2(-4.3,1.27) 3(-4.3,-1.27) 4(-4.3,-3.81) 5(4.3,-3.81) 6(4.3,-1.27) 7(4.3,1.27) 8(4.3,3.81)
ASF_SMD3_2X5MM
  rect 1.5x1.7 smd: 1(-1.1,1.27) 2(-1.1,-1.27) 3(1.1,-1.27) 4(1.1,1.27)
DCT8
  rect 1.6x0.3 smd: 1(-1.7,0.975) 2(-1.7,0.325) 3(-1.7,-0.325) 4(-1.7,-0.975) 5(1.7,-0.975) 6(1.7,-0.325) 7(1.7,0.325) 8(1.7,0.975)
ECS_SMD3_2X5MM
  rect 1.5x1.6 smd: 1(-1.15,1.25) 2(-1.15,-1.25) 3(1.15,-1.25) 4(1.15,1.25)
FBGA324
  round 0.483 smd: A1(-8.5,8.5) A2(-7.5,8.5) A3(-6.5,8.5) A4(-5.5,8.5) A5(-4.5,8.5) A6(-3.5,8.5) A7(-2.5,8.5) A8(-1.5,8.5) A9(-0.5,8.5) A10(0.5,8.5) A11(1.5,8.5) A12(2.5,8.5) A13(3.5,8.5) A14(4.5,8.5) A15(5.5,8.5) A16(6.5,8.5) A17(7.5,8.5) A18(8.5,8.5) B1(-8.5,7.5) B2(-7.5,7.5) B3(-6.5,7.5) B4(-5.5,7.5) B5(-4.5,7.5) B6(-3.5,7.5) B7(-2.5,7.5) B8(-1.5,7.5) B9(-0.5,7.5) B10(0.5,7.5) B11(1.5,7.5) B12(2.5,7.5) B13(3.5,7.5) B14(4.5,7.5) B15(5.5,7.5) B16(6.5,7.5) B17(7.5,7.5) B18(8.5,7.5) C1(-8.5,6.5) C2(-7.5,6.5) C3(-6.5,6.5) C4(-5.5,6.5) C5(-4.5,6.5) C6(-3.5,6.5) C7(-2.5,6.5) C8(-1.5,6.5) C9(-0.5,6.5) C10(0.5,6.5) C11(1.5,6.5) C12(2.5,6.5) C13(3.5,6.5) C14(4.5,6.5) C15(5.5,6.5) C16(6.5,6.5) C17(7.5,6.5) C18(8.5,6.5) D1(-8.5,5.5) D2(-7.5,5.5) D3(-6.5,5.5) D4(-5.5,5.5) D5(-4.5,5.5) D6(-3.5,5.5) D7(-2.5,5.5) D8(-1.5,5.5) D9(-0.5,5.5) D10(0.5,5.5) D11(1.5,5.5) D12(2.5,5.5) D13(3.5,5.5) D14(4.5,5.5) D15(5.5,5.5) D16(6.5,5.5) D17(7.5,5.5) D18(8.5,5.5) E1(-8.5,4.5) E2(-7.5,4.5) E3(-6.5,4.5) E4(-5.5,4.5) E5(-4.5,4.5) E6(-3.5,4.5) E7(-2.5,4.5) E8(-1.5,4.5) E9(-0.5,4.5) E10(0.5,4.5) E11(1.5,4.5) E12(2.5,4.5) E13(3.5,4.5) E14(4.5,4.5) E15(5.5,4.5) E16(6.5,4.5) E17(7.5,4.5) E18(8.5,4.5) F1(-8.5,3.5) F2(-7.5,3.5) F3(-6.5,3.5) F4(-5.5,3.5) F5(-4.5,3.5) F6(-3.5,3.5) F7(-2.5,3.5) F8(-1.5,3.5) F9(-0.5,3.5) F10(0.5,3.5) F11(1.5,3.5) F12(2.5,3.5) F13(3.5,3.5) F14(4.5,3.5) F15(5.5,3.5) F16(6.5,3.5) F17(7.5,3.5) F18(8.5,3.5) G1(-8.5,2.5) G2(-7.5,2.5) G3(-6.5,2.5) G4(-5.5,2.5) G5(-4.5,2.5) G6(-3.5,2.5) G7(-2.5,2.5) G8(-1.5,2.5) G9(-0.5,2.5) G10(0.5,2.5) G11(1.5,2.5) G12(2.5,2.5) G13(3.5,2.5) G14(4.5,2.5) G15(5.5,2.5) G16(6.5,2.5) G17(7.5,2.5) G18(8.5,2.5) H1(-8.5,1.5) H2(-7.5,1.5) H3(-6.5,1.5) H4(-5.5,1.5) H5(-4.5,1.5) H6(-3.5,1.5) H7(-2.5,1.5) H8(-1.5,1.5) H9(-0.5,1.5) H10(0.5,1.5) H11(1.5,1.5) H12(2.5,1.5) H13(3.5,1.5) H14(4.5,1.5) H15(5.5,1.5) H16(6.5,1.5) H17(7.5,1.5) H18(8.5,1.5) J1(-8.5,0.5) J2(-7.5,0.5) J3(-6.5,0.5) J4(-5.5,0.5) J5(-4.5,0.5) J6(-3.5,0.5) J7(-2.5,0.5) J8(-1.5,0.5) J9(-0.5,0.5) J10(0.5,0.5) J11(1.5,0.5) J12(2.5,0.5) J13(3.5,0.5) J14(4.5,0.5) J15(5.5,0.5) J16(6.5,0.5) J17(7.5,0.5) J18(8.5,0.5) K1(-8.5,-0.5) K2(-7.5,-0.5) K3(-6.5,-0.5) K4(-5.5,-0.5) K5(-4.5,-0.5) K6(-3.5,-0.5) K7(-2.5,-0.5) K8(-1.5,-0.5) K9(-0.5,-0.5) K10(0.5,-0.5) K11(1.5,-0.5) K12(2.5,-0.5) K13(3.5,-0.5) K14(4.5,-0.5) K15(5.5,-0.5) K16(6.5,-0.5) K17(7.5,-0.5) K18(8.5,-0.5) L1(-8.5,-1.5) L2(-7.5,-1.5) L3(-6.5,-1.5) L4(-5.5,-1.5) L5(-4.5,-1.5) L6(-3.5,-1.5) L7(-2.5,-1.5) L8(-1.5,-1.5) L9(-0.5,-1.5) L10(0.5,-1.5) L11(1.5,-1.5) L12(2.5,-1.5) L13(3.5,-1.5) L14(4.5,-1.5) L15(5.5,-1.5) L16(6.5,-1.5) L17(7.5,-1.5) L18(8.5,-1.5) M1(-8.5,-2.5) M2(-7.5,-2.5) M3(-6.5,-2.5) M4(-5.5,-2.5) M5(-4.5,-2.5) M6(-3.5,-2.5) M7(-2.5,-2.5) M8(-1.5,-2.5) M9(-0.5,-2.5) M10(0.5,-2.5) M11(1.5,-2.5) M12(2.5,-2.5) M13(3.5,-2.5) M14(4.5,-2.5) M15(5.5,-2.5) M16(6.5,-2.5) M17(7.5,-2.5) M18(8.5,-2.5) N1(-8.5,-3.5) N2(-7.5,-3.5) N3(-6.5,-3.5) N4(-5.5,-3.5) N5(-4.5,-3.5) N6(-3.5,-3.5) N7(-2.5,-3.5) N8(-1.5,-3.5) N9(-0.5,-3.5) N10(0.5,-3.5) N11(1.5,-3.5) N12(2.5,-3.5) N13(3.5,-3.5) N14(4.5,-3.5) N15(5.5,-3.5) N16(6.5,-3.5) N17(7.5,-3.5) N18(8.5,-3.5) P1(-8.5,-4.5) P2(-7.5,-4.5) P3(-6.5,-4.5) P4(-5.5,-4.5) P5(-4.5,-4.5) P6(-3.5,-4.5) P7(-2.5,-4.5) P8(-1.5,-4.5) P9(-0.5,-4.5) P10(0.5,-4.5) P11(1.5,-4.5) P12(2.5,-4.5) P13(3.5,-4.5) P14(4.5,-4.5) P15(5.5,-4.5) P16(6.5,-4.5) P17(7.5,-4.5) P18(8.5,-4.5) R1(-8.5,-5.5) R2(-7.5,-5.5) R3(-6.5,-5.5) R4(-5.5,-5.5) R5(-4.5,-5.5) R6(-3.5,-5.5) R7(-2.5,-5.5) R8(-1.5,-5.5) R9(-0.5,-5.5) R10(0.5,-5.5) R11(1.5,-5.5) R12(2.5,-5.5) R13(3.5,-5.5) R14(4.5,-5.5) R15(5.5,-5.5) R16(6.5,-5.5) R17(7.5,-5.5) R18(8.5,-5.5) T1(-8.5,-6.5) T2(-7.5,-6.5) T3(-6.5,-6.5) T4(-5.5,-6.5) T5(-4.5,-6.5) T6(-3.5,-6.5) T7(-2.5,-6.5) T8(-1.5,-6.5) T9(-0.5,-6.5) T10(0.5,-6.5) T11(1.5,-6.5) T12(2.5,-6.5) T13(3.5,-6.5) T14(4.5,-6.5) T15(5.5,-6.5) T16(6.5,-6.5) T17(7.5,-6.5) T18(8.5,-6.5) U1(-8.5,-7.5) U2(-7.5,-7.5) U3(-6.5,-7.5) U4(-5.5,-7.5) U5(-4.5,-7.5) U6(-3.5,-7.5) U7(-2.5,-7.5) U8(-1.5,-7.5) U9(-0.5,-7.5) U10(0.5,-7.5) U11(1.5,-7.5) U12(2.5,-7.5) U13(3.5,-7.5) U14(4.5,-7.5) U15(5.5,-7.5) U16(6.5,-7.5) U17(7.5,-7.5) U18(8.5,-7.5) V1(-8.5,-8.5) V2(-7.5,-8.5) V3(-6.5,-8.5) V4(-5.5,-8.5) V5(-4.5,-8.5) V6(-3.5,-8.5) V7(-2.5,-8.5) V8(-1.5,-8.5) V9(-0.5,-8.5) V10(0.5,-8.5) V11(1.5,-8.5) V12(2.5,-8.5) V13(3.5,-8.5) V14(4.5,-8.5) V15(5.5,-8.5) V16(6.5,-8.5) V17(7.5,-8.5) V18(8.5,-8.5)
FTR-106-53-G-D-06
  rect 0.711x2.87 smd: 1(-5.715,2.375) 2(-5.715,7.785) 3(-4.445,2.375) 4(-4.445,7.785) 5(-3.175,2.375) 6(-3.175,7.785) 7(-1.905,2.375) 8(-1.905,7.785) 9(-0.635,2.375) 10(-0.635,7.785) 11(0.635,2.375) 12(0.635,7.785)
HEADER_10X2_TH
  oval 0.914x1.168 hole 0.66: 1(0,0) 2(0,1.27) 3(1.27,0) 4(1.27,1.27) 5(2.54,0) 6(2.54,1.27) 7(3.81,0) 8(3.81,1.27) 9(5.08,0) 10(5.08,1.27) 11(6.35,0) 12(6.35,1.27) 13(7.62,0) 14(7.62,1.27) 15(8.89,0) 16(8.89,1.27) 17(10.16,0) 18(10.16,1.27) 19(11.43,0) 20(11.43,1.27)
HEADER_10X2_TH_LCD
  oval 0.914x1.168 hole 0.66: 1(0,1.27) 2(0,0) 3(1.27,1.27) 4(1.27,0) 5(2.54,1.27) 6(2.54,0) 7(3.81,1.27) 8(3.81,0) 9(5.08,1.27) 10(5.08,0) 11(6.35,1.27) 12(6.35,0) 13(7.62,1.27) 14(7.62,0) 15(8.89,1.27) 16(8.89,0) 17(10.16,1.27) 18(10.16,0) 19(11.43,1.27) 20(11.43,0)
JUMP2X10-6040-1
  round 1.524 hole 1.016: 1(0,0) 2(0,2.54) 3(-2.54,0) 4(-2.54,2.54) 5(-5.08,0) 6(-5.08,2.54) 7(-7.62,0) 8(-7.62,2.54) 9(-10.16,0) 10(-10.16,2.54) 11(-12.7,0) 12(-12.7,2.54) 13(-15.24,0) 14(-15.24,2.54) 15(-17.78,0) 16(-17.78,2.54) 17(-20.32,0) 18(-20.32,2.54) 19(-22.86,0) 20(-22.86,2.54)
JUMP2X14-6040-1
  round 1.524 hole 1.016: 1(0,0) 2(0,2.54) 3(-2.54,0) 4(-2.54,2.54) 5(-5.08,0) 6(-5.08,2.54) 7(-7.62,0) 8(-7.62,2.54) 9(-10.16,0) 10(-10.16,2.54) 11(-12.7,0) 12(-12.7,2.54) 13(-15.24,0) 14(-15.24,2.54) 15(-17.78,0) 16(-17.78,2.54) 17(-20.32,0) 18(-20.32,2.54) 19(-22.86,0) 20(-22.86,2.54) 21(-25.4,0) 22(-25.4,2.54) 23(-27.94,0) 24(-27.94,2.54) 25(-30.48,0) 26(-30.48,2.54) 27(-33.02,0) 28(-33.02,2.54)
JUMP2X20-6040-1
  round 1.524 hole 1.016: 1(0,0) 2(0,2.54) 3(-2.54,0) 4(-2.54,2.54) 5(-5.08,0) 6(-5.08,2.54) 7(-7.62,0) 8(-7.62,2.54) 9(-10.16,0) 10(-10.16,2.54) 11(-12.7,0) 12(-12.7,2.54) 13(-15.24,0) 14(-15.24,2.54) 15(-17.78,0) 16(-17.78,2.54) 17(-20.32,0) 18(-20.32,2.54) 19(-22.86,0) 20(-22.86,2.54) 21(-25.4,0) 22(-25.4,2.54) 23(-27.94,0) 24(-27.94,2.54) 25(-30.48,0) 26(-30.48,2.54) 27(-33.02,0) 28(-33.02,2.54) 29(-35.56,0) 30(-35.56,2.54) 31(-38.1,0) 32(-38.1,2.54) 33(-40.64,0) 34(-40.64,2.54) 35(-43.18,0) 36(-43.18,2.54) 37(-45.72,0) 38(-45.72,2.54) 39(-48.26,0) 40(-48.26,2.54)
LGA16PIN_3X3
  rect 0.45x0.35 smd: 1(-1.25,1) 2(-1.25,0.5) 3(-1.25,0) 4(-1.25,-0.5) 5(-1.25,-1) 9(1.25,-1) 10(1.25,-0.5) 11(1.25,0) 12(1.25,0.5) 13(1.25,1)
  rect 0.35x0.45 smd: 6(-0.5,-1.25) 7(0,-1.25) 8(0.5,-1.25) 14(0.5,1.25) 15(0,1.25) 16(-0.5,1.25)
MHC-W21-601-LF
  round 1.524 hole 1.092: (-11.5,-3.05)
  round 2.108 hole 1.6: (9.5,-3.05)
  rect 0.6x2 smd: 1(6.875,0) 2(4.375,0) 3(1.875,0) 4(-0.625,0) 5(-3.125,0) 6(-5.625,0) 7(-8.05,0) 8(-9.75,0) 9(9.375,0)
  rect 1x1.5 smd: 10(5.65,-17) 11(3.15,-17) 12(-4.35,-17) 13(-6.85,-17)
  rect 0.7x2 smd: 14(-12.25,0) 15(-11.05,0)
  rect 0.5x2 smd: 16(-7.27,0) 17(-6.475,0) 18(-4.775,0) 19(-1.475,0) 20(0.225,0) 21(1.025,0) 22(2.725,0) 23(3.525,0) 24(-8.9,0) 25(-3.975,0) 26(-2.275,0)
  rect 1.3x2.4 smd: 27(-14.15,-17.05) 28(14.15,-17.05)
MOL-015-91-0100
  rect 1.27x3.683 smd: 1(-5.08,-2.223) 2(-5.08,2.223) 3(-2.54,-2.223) 4(-2.54,2.223) 5(0,-2.223) 6(0,2.223) 7(2.54,-2.223) 8(2.54,2.223) 9(5.08,-2.223) 10(5.08,2.223)
MSOP_DGK
  rect 1.6x0.4 smd: 1(-2.1,0.975) 2(-2.1,0.325) 3(-2.1,-0.325) 4(-2.1,-0.975) 5(2.1,-0.975) 6(2.1,-0.325) 7(2.1,0.325) 8(2.1,0.975)
NORCOMP_DB9M_SMD
  round 2.007 hole 1.499 unplated: (-7.95,-0.66) (7.95,-0.66)
  rect 0.8x3.5 smd: 1(5.537,0) 2(2.769,0) 3(0,0) 4(-2.769,0) 5(-5.537,0) 6(4.153,0) 7(1.384,0) 8(-1.384,0) 9(-4.153,0)
  round 5.08 hole 3.048: 10(-12.497,-0.66) 11(12.497,-0.66)
NORCOMP_DB9M_TH
  rect 1.6x1.6 hole 1.092: 1(0.051,0)
  round 1.6 hole 1.092: 2(-2.718,0) 3(-5.486,0) 4(-8.255,0) 5(-11.024,0) 6(-1.346,2.845) 7(-4.102,2.845) 8(-6.871,2.845) 9(-9.639,2.845)
  round 5.08 hole 3.048: 10(-17.983,1.422) 11(7.01,1.422)
PICO_304-100
  rect 1.27x1.27 hole 0.762: 1(1.15,5)
  round 1.27 hole 0.762: 2(-1.15,5)
  round 2.75 hole 1.092: M1(0,2.3) M2(0,-5.4)
RSZ
  rect 1.85x1.2 smd: 1(-5.45,5.08) 2(-5.45,2.54) 4(-5.45,-2.54) 5(-5.45,-5.08) 7(5.45,-2.54) 10(5.45,5.08)
SJ3524SMT4PIN
  round 1.702 hole 1.702 unplated: (-8.1,-3.95) (-1.1,-3.95)
  rect 2.21x2.794 smd: 1(0,-0.253) 3(-2,-7.647)
  rect 2.794x2.794 smd: 2(-9.4,-0.253) 10(-13.5,-4.703)
SKT-TSOP48SM
  rect 1.524x0.305 smd: 1(-9.716,5.753) 2(-9.716,5.253) 3(-9.716,4.752) 4(-9.716,4.252) 5(-9.716,3.754) 6(-9.716,3.254) 7(-9.716,2.753) 8(-9.716,2.253) 9(-9.716,1.753) 10(-9.716,1.252) 11(-9.716,0.754) 12(-9.716,0.254) 13(-9.716,-0.246) 14(-9.716,-0.747) 15(-9.716,-1.247) 16(-9.716,-1.748) 17(-9.716,-2.248) 18(-9.716,-2.746) 19(-9.716,-3.246) 20(-9.716,-3.747) 21(-9.716,-4.247) 22(-9.716,-4.747) 23(-9.716,-5.248) 24(-9.716,-5.748) 25(9.716,-5.753) 26(9.716,-5.253) 27(9.716,-4.752) 28(9.716,-4.252) 29(9.716,-3.754) 30(9.716,-3.254) 31(9.716,-2.753) 32(9.716,-2.253) 33(9.716,-1.753) 34(9.716,-1.252) 35(9.716,-0.754) 36(9.716,-0.254) 37(9.716,0.246) 38(9.716,0.747) 39(9.716,1.247) 40(9.716,1.748) 41(9.716,2.248) 42(9.716,2.746) 43(9.716,3.246) 44(9.716,3.747) 45(9.716,4.247) 46(9.716,4.747) 47(9.716,5.248) 48(9.716,5.748)
SM-7351-CAP-0402
  round 0.635 smd: 1(-0.508,0) 2(0.508,0)
SM-7351-CAP-0603
  rect 1.092x1.041 smd: 1(-0.85,0) 2(0.85,0)
SM-7351-CAP-0805
  rect 1.346x1.524 smd: 1(-1,0) 2(1,0)
SM-7351-CAP-1206
  rect 1.2x1.85 smd: 1(1.6,0) 2(-1.6,0)
SM-7351-IND-0805
  rect 1.397x1.549 smd: 1(-0.95,0) 2(0.95,0)
SM-7351-RES-0402
  round 0.635 smd: 1(-0.508,0) 2(0.508,0)
SM-7351-RES-0603
  rect 1.143x1.092 smd: 1(-0.9,0) 2(0.9,0)
SM-SOT-23
  rect 1.397x0.991 smd: 1(1.1,-0.95) 2(1.1,0.95) 3(-1.1,0)
SM_LED_0805
  rect 1.15x1.194 smd: 1(1.125,0) 2(-1.125,0)
SO8_W_DUB
  rect 0.61x2.184 smd: 1(-1.905,-3.873)
  oval 0.61x2.184 smd: 2(0.635,-3.873) 3(3.175,-3.873) 4(5.715,-3.873) 5(5.715,3.873) 6(3.175,3.873) 7(0.635,3.873) 8(-1.905,3.873)
SOIC_8
  rect 0.61x2.184 smd: 1(-1.905,-3.619)
  oval 0.61x2.184 smd: 2(-0.635,-3.619) 3(0.635,-3.619) 4(1.905,-3.619) 5(1.905,3.619) 6(0.635,3.619) 7(-0.635,3.619) 8(-1.905,3.619)
SOT23-3
  rect 0.787x0.889 smd: D(0,1.003) G(-0.94,-1.003) S(0.94,-1.003)
SOT223_6PIN
  rect 0.991x1.499 smd: 1(-2.54,-3.15) 2(-1.27,-3.15) 3(0,-3.15) 4(1.27,-3.15) 5(2.54,-3.15)
  rect 3.277x1.499 smd: 6(0,3.15)
SPKR_AI_1027
  rect 1.575x1.575 hole 1.016: 1(0,0)
  round 1.575 hole 1.016: 2(5,0)
SW_B3SL-1022P
  rect 2.75x1 smd: 1(2.875,-2) 2(-2.875,-2) 3(2.875,2) 4(-2.875,2)
T_SMD-4
  rect 0.8x1 smd: 1(-1.45,0.75) 2(-1.45,-0.75) 3(1.45,-0.75) 4(1.45,0.75)
TBGA64
  round 0.406 smd: A1(-3.5,3.5) A2(-2.5,3.5) A3(-1.5,3.5) A4(-0.5,3.5) A5(0.5,3.5) A6(1.5,3.5) A7(2.5,3.5) A8(3.5,3.5) B1(-3.5,2.5) B2(-2.5,2.5) B3(-1.5,2.5) B4(-0.5,2.5) B5(0.5,2.5) B6(1.5,2.5) B7(2.5,2.5) B8(3.5,2.5) C1(-3.5,1.5) C2(-2.5,1.5) C3(-1.5,1.5) C4(-0.5,1.5) C5(0.5,1.5) C6(1.5,1.5) C7(2.5,1.5) C8(3.5,1.5) D1(-3.5,0.5) D2(-2.5,0.5) D3(-1.5,0.5) D4(-0.5,0.5) D5(0.5,0.5) D6(1.5,0.5) D7(2.5,0.5) D8(3.5,0.5) E1(-3.5,-0.5) E2(-2.5,-0.5) E3(-1.5,-0.5) E4(-0.5,-0.5) E5(0.5,-0.5) E6(1.5,-0.5) E7(2.5,-0.5) E8(3.5,-0.5) F1(-3.5,-1.5) F2(-2.5,-1.5) F3(-1.5,-1.5) F4(-0.5,-1.5) F5(0.5,-1.5) F6(1.5,-1.5) F7(2.5,-1.5) F8(3.5,-1.5) G1(-3.5,-2.5) G2(-2.5,-2.5) G3(-1.5,-2.5) G4(-0.5,-2.5) G5(0.5,-2.5) G6(1.5,-2.5) G7(2.5,-2.5) G8(3.5,-2.5) H1(-3.5,-3.5) H2(-2.5,-3.5) H3(-1.5,-3.5) H4(-0.5,-3.5) H5(0.5,-3.5) H6(1.5,-3.5) H7(2.5,-3.5) H8(3.5,-3.5)
TECONN_221789
  round 2.54 hole 1.524: 1(0,0)
  round 2.311 hole 1.702: 2(-2.54,-2.54) 3(2.54,-2.54) 4(-2.54,2.54) 5(2.54,2.54)
TH_TP_5002
  round 1.778 hole 1.016: 1(0,0)
TP_SMD1MMCIRCLE
  round 1.016 smd: 1(0,0)
TVSOP-DGV
  rect 1.8x0.28 smd: 1(-2.86,4.6) 2(-2.86,4.2) 3(-2.86,3.8) 4(-2.86,3.4) 5(-2.86,3) 6(-2.86,2.6) 7(-2.86,2.2) 8(-2.86,1.8) 9(-2.86,1.4) 10(-2.86,1) 11(-2.86,0.6) 12(-2.86,0.2) 13(-2.86,-0.2) 14(-2.86,-0.6) 15(-2.86,-1) 16(-2.86,-1.4) 17(-2.86,-1.8) 18(-2.86,-2.2) 19(-2.86,-2.6) 20(-2.86,-3) 21(-2.86,-3.4) 22(-2.86,-3.8) 23(-2.86,-4.2) 24(-2.86,-4.6) 25(2.86,-4.6) 26(2.86,-4.2) 27(2.86,-3.8) 28(2.86,-3.4) 29(2.86,-3) 30(2.86,-2.6) 31(2.86,-2.2) 32(2.86,-1.8) 33(2.86,-1.4) 34(2.86,-1) 35(2.86,-0.6) 36(2.86,-0.2) 37(2.86,0.2) 38(2.86,0.6) 39(2.86,1) 40(2.86,1.4) 41(2.86,1.8) 42(2.86,2.2) 43(2.86,2.6) 44(2.86,3) 45(2.86,3.4) 46(2.86,3.8) 47(2.86,4.2) 48(2.86,4.6)
U_5_DRL
  rect 0.3x0.45 smd: 1(-0.5,-0.675) 2(0,-0.675) 3(0.5,-0.675) 4(0.5,0.675) 5(-0.5,0.675)
U_6_DCK
  rect 0.432x1.27 smd: 1(0.65,0.775) 2(0,0.775) 3(-0.65,0.775) 4(-0.65,-0.884) 5(0,-0.884) 6(0.65,-0.884)
U_10_RSE
  rect 0.3x0.58 smd: 1(-0.75,-0.635) 2(-0.25,-0.635) 3(0.25,-0.635) 4(0.75,-0.635) 6(0.75,0.635) 7(0.25,0.635) 8(-0.25,0.635) 9(-0.75,0.635)
  rect 0.63x0.35 smd: 5(0.86,0) 10(-0.86,0)
U_16_D
  rect 0.6x2 smd: 1(-4.445,-2.4) 2(-3.175,-2.4) 3(-1.905,-2.4) 4(-0.635,-2.4) 5(0.635,-2.4) 6(1.905,-2.4) 7(3.175,-2.4) 8(4.445,-2.4) 9(4.445,2.4) 10(3.175,2.4) 11(1.905,2.4) 12(0.635,2.4) 13(-0.635,2.4) 14(-1.905,2.4) 15(-3.175,2.4) 16(-4.445,2.4)
U_16_PW
  rect 0.35x1.6 smd: 1(-2.275,-2.8) 2(-1.625,-2.8) 3(-0.975,-2.8) 4(-0.325,-2.8) 5(0.325,-2.8) 6(0.975,-2.8) 7(1.625,-2.8) 8(2.275,-2.8) 9(2.275,2.8) 10(1.625,2.8) 11(0.975,2.8) 12(0.325,2.8) 13(-0.325,2.8) 14(-0.975,2.8) 15(-1.625,2.8) 16(-2.275,2.8)
U_24_RTW
  rect 0.85x0.28 smd: 1(-1.975,1.25) 2(-1.975,0.75) 3(-1.975,0.25) 4(-1.975,-0.25) 5(-1.975,-0.75) 6(-1.975,-1.25) 13(1.975,-1.25) 14(1.975,-0.75) 15(1.975,-0.25) 16(1.975,0.25) 17(1.975,0.75) 18(1.975,1.25)
  rect 0.28x0.85 smd: 7(-1.25,-1.975) 8(-0.75,-1.975) 9(-0.25,-1.975) 10(0.25,-1.975) 11(0.75,-1.975) 12(1.25,-1.975) 19(1.25,1.975) 20(0.75,1.975) 21(0.25,1.975) 22(-0.25,1.975) 23(-0.75,1.975) 24(-1.25,1.975)
  rect 2.45x2.45 smd: TPAD(0,0)
unnamed#2
  round 1.27 hole 6.35 unplated: (0,0)
VQFN48_RGZ
  rect 0.85x0.28 smd: 1(-3.475,2.75) 2(-3.475,2.25) 3(-3.475,1.75) 4(-3.475,1.25) 5(-3.475,0.75) 6(-3.475,0.25) 7(-3.475,-0.25) 8(-3.475,-0.75) 9(-3.475,-1.25) 10(-3.475,-1.75) 11(-3.475,-2.25) 12(-3.475,-2.75) 25(3.475,-2.75) 26(3.475,-2.25) 27(3.475,-1.75) 28(3.475,-1.25) 29(3.475,-0.75) 30(3.475,-0.25) 31(3.475,0.25) 32(3.475,0.75) 33(3.475,1.25) 34(3.475,1.75) 35(3.475,2.25) 36(3.475,2.75)
  rect 0.28x0.85 smd: 13(-2.75,-3.475) 14(-2.25,-3.475) 15(-1.75,-3.475) 16(-1.25,-3.475) 17(-0.75,-3.475) 18(-0.25,-3.475) 19(0.25,-3.475) 20(0.75,-3.475) 21(1.25,-3.475) 22(1.75,-3.475) 23(2.25,-3.475) 24(2.75,-3.475) 37(2.75,3.475) 38(2.25,3.475) 39(1.75,3.475) 40(1.25,3.475) 41(0.75,3.475) 42(0.25,3.475) 43(-0.25,3.475) 44(-0.75,3.475) 45(-1.25,3.475) 46(-1.75,3.475) 47(-2.25,3.475) 48(-2.75,3.475)
  rect 5.15x5.15 smd: TPAD(0,0)

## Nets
AGND_AUD: C199.2 C200.2 C201.2 C202.2 C203.2 C204.2 C205.2 C206.2 C207.2 C208.2 C210.2 C212.2 C213.2 C214.2 C215.2 C216.2 C221.2 C222.2 C223.2 C224.2 FB8.1 J26.1(P1) J27.1(P1) U51.15(AVSS_ADC) U51.20(DRVSS#20) U51.21(DRVSS#21) U51.26(AVSS_DAC) U51.TPAD
DGND: C1.2 C2.2 C3.2 C4.2 C5.2 C6.2 C7.2 C8.2 C9.2 C10.2 C11.2 C12.2 C13.2 C14.2 C15.2 C16.2 C17.2 C18.2 C19.2 C20.2 C21.2 C22.2 C23.2 C24.2 C25.2 C26.2 C27.2 C28.2 C29.2 C30.2 C31.2 C32.2 C33.2 C34.2 C35.2 C36.2 C37.2 C38.2 C39.2 C40.2 C41.2 C42.2 C43.2 C44.2 C45.2 C46.2 C47.2 C48.2 C49.2 C51.2 C53.2 C56.2 C57.2 C58.2 C59.2 C60.2 C63.2 C68.2 C69.2 C70.2 C74.2 C76.2 C77.2 C78.2 C79.2 C80.2 C81.2 C121.2 C122.2 C123.2 C124.2 C125.2 C126.2 C127.2 C128.2 C129.2 C130.2 C131.2 C132.2 C133.2 C134.2 C135.2 C136.2 C137.2 C138.2 C139.2 C140.2 C141.2 C142.2 C143.2 C144.2 C145.2 C146.2 C147.2 C148.2 C149.2 C150.2 C151.2 C152.2 C153.2 C154.2 C155.2 C156.2 C157.2 C158.2 C159.2 C160.2 C161.2 C162.2 C163.2 C164.2 C165.2 C166.2 C217.2 C218.2 C219.2 C220.2 C226.2 C227.2 C229.2 C230.2 FB8.2 J1.27 J1.28 J2.7 J2.8 J3.1 J3.10 J3.11 J3.20 J3.30 J3.37 J4.3 J4.14 J4.20 J4.25 J5.19 J5.20 J6.19 J6.20 J7.10 J10.5 J10.10 J10.11 J12.5 J12.10 J12.11 J14.5 J14.10 J14.11 J15.3(#3_MMC+/MMCM/RSMMC/MMC/SD) J15.6(#6_MMC+/MMCM/RSMMC/MMC/SD) J15.18(#3_MINISD) J15.21(#6_MINISD) J15.27(GND1) J15.28(GND2) J18.9 J18.10 J19.19 J19.20 J20.19 J20.20 J21.10 J22.2 J22.10 Q1.S(SOURCE) Q2.S(SOURCE) Q3.S(SOURCE) Q4.S(SOURCE) Q5.S(SOURCE) Q6.S(SOURCE) Q7.S(SOURCE) Q8.S(SOURCE) Q9.S(SOURCE) Q10.S(SOURCE) Q11.S(SOURCE) Q12.S(SOURCE) Q13.S(SOURCE) Q14.S(SOURCE) Q15.S(SOURCE) Q16.S(SOURCE) Q17.S(SOURCE) Q18.S(SOURCE) R10.1(P1) R11.1(P1) R13.1(P1) R17.1(P1) R26.1(P1) R27.1(P1) R30.1(P1) R32.1(P1) R33.1(P1) R103.1(P1) R112.1(P1) R113.1(P1) R114.1(P1) R115.1(P1) R116.1(P1) R117.1(P1) R118.1(P1) R119.1(P1) R121.1(P1) R122.1(P1) R123.1(P1) R124.1(P1) R128.1(P1) R137.1(P1) R138.1(P1) R139.1(P1) R140.1(P1) R141.1(P1) R142.1(P1) R143.1(P1) R144.1(P1) R146.1(P1) R148.1(P1) R149.1(P1) R150.1(P1) R151.1(P1) R152.1(P1) R159.1(P1) R229.1(P1) R240.1(P1) R244.1(P1) R259.1(P1) SW7.3 SW7.4 SW9.3 SW9.4 SW10.3 SW10.4 TP38.1 TP39.1 TP40.1 TP41.1 U1.2(A1) U1.3(A2) U1.4(VSS) U2.4(GND#4) U2.10(GND#10) U2.15(GND#15) U2.21(GND#21) U2.28(GND#28) U2.34(GND#34) U2.39(GND#39) U2.45(GND#45) U3.E8(VSS#E8) U3.H2(VSS#H2) U3.H7(VSS#H7) U4.4(GND#4) U4.10(GND#10) U4.15(GND#15) U4.21(GND#21) U4.28(GND#28) U4.34(GND#34) U4.39(GND#39) U4.45(GND#45) U5.13(GND#13) U5.25(GND#25) U5.36(GND#36) U5.48(GND#48) U6.4(GND#4) U6.10(GND#10) U6.15(GND#15) U6.21(GND#21) U6.28(GND#28) U6.34(GND#34) U6.39(GND#39) U6.45(GND#45) U7.4(GND#4) U7.10(GND#10) U7.15(GND#15) U7.21(GND#21) U7.28(GND#28) U7.34(GND#34) U7.39(GND#39) U7.45(GND#45) U8.4(GND) U9.5(GND#5) U9.10(RSV0) U9.12(GND#12) U9.13(GND#13) U9.16(GND#16) U10.2(GND) U11.2(GND) U12.2(GND) U13.4(GND) U13.5(A2) U14.1(VIN-) U15.15(GND) U16.4(GND1) U19.15(GND) U22.15(GND) U23.2(GND#2) U23.11(GND#11) U23.TPAD U25.5(GND) U26.5(GND) U27.4(GND) U39.8(GND) U40.8(GND) U41.M1 U41.M2 U42.2(GND) U42.3(2A) U43.A1(GNDIO#A1) U43.A18(GNDIO#A18) U43.B2(GNDIO#B2) U43.B17(GNDIO#B17) U43.G8(GNDINT#G8) U43.H7(GNDINT#H7) U43.H8(GNDIO#H8) U43.H9(GNDIO#H9) U43.H10(GNDIO#H10) U43.H11(GNDIO#H11) U43.J8(GNDINT#J8) U43.J10(GNDINT#J10) U43.K9(GNDINT#K9) U43.K11(GNDINT#K11) U43.L8(GNDIO#L8) U43.L9(GNDIO#L9) U43.L10(GNDIO#L10) U43.L11(GNDIO#L11) U43.L12(GNDINT#L12) U43.M11(GNDINT#M11) U43.U2(GNDIO#U2) U43.U17(GNDIO#U17) U43.V1(GNDIO#V1) U43.V18(GNDIO#V18) U51.42(DVSS) U51.43(SELECT) U52.3(GND#3) U52.6(GND#6) U53.3(GND#3) U53.6(GND#6) Y2.2(GND) Y5.2(GND)
GND_CAN0: C52.2 C54.2 J11.3 J11.5 J11.6 J11.10 J11.11 U14.4(VOUT-#4) U14.5(VOUT-#5) U16.5(GND2) U17.3
GNDA_TSC: J7.11 J7.12 J8.5 J8.6 J8.11 J8.12 J9.2 J9.3 J9.4 J9.5 J21.11 J21.12
V1_8D: C3.1 C10.1 C124.1 C133.1 C219.1 C220.1 J1.1 J6.2 J20.2 R6.1(P1) R7.1(P1) R8.1(P1) R9.1(P1) R126.2(P2) R162.2(P2) R164.2(P2) R166.2(P2) R168.2(P2) R241.1(P1) U40.16(VCCP) U51.36(DVDD)
V3_3AUD: C203.1 C204.1 C213.1 C214.1 C215.1 C216.1 FB9.2 U51.16(DRVDD#16) U51.17(DRVDD#17) U51.24(DRVDD#24) U51.25(AVDD_DAC)
V3_3D: C4.1 C5.1 C12.1 C15.1 C16.1 C17.1 C18.1 C19.1 C20.1 C27.1 C29.1 C32.1 C33.1 C34.1 C39.1 C41.1 C42.1 C43.1 C45.1 C46.1 C47.1 C48.1 C49.1 C51.1 C59.1 C60.1 C69.1 C70.1 C121.1 C122.1 C123.1 C128.1 C135.1 C136.1 C217.1 C218.1 FB9.1 J3.39 J4.15 J7.2 J21.2 R2.1(P1) R3.1(P1) R4.1(P1) R5.1(P1) R14.2(P2) R15.2(P2) R16.2(P2) R21.2(P2) R22.2(P2) R23.2(P2) R24.2(P2) R25.2(P2) R31.2(P2) R57.2(P2) R100.2(P2) R101.2(P2) R102.2(P2) R127.2(P2) R160.2(P2) R161.2(P2) R163.2(P2) R165.2(P2) R167.2(P2) R235.2(P2) R236.2(P2) R237.1(P1) SW8.5 SW8.6 SW8.7 SW8.8 U2.7(VCCB#7) U2.18(VCCB#18) U3.D8(VCCQ#D8) U3.F1(VCCQ#F1) U3.G5(VCC) U4.7(VCCB#7) U4.18(VCCB#18) U6.7(VCCB#7) U6.18(VCCB#18) U8.8(VCC) U9.1(VDD_IO) U9.14(VDD) U9.15(RSV1) U10.7(VCCB) U11.7(VCCB) U12.1(VDD) U13.8(V+) U14.2(VIN+) U15.16(VCC) U16.1(VCC1) U19.16(VCC) U22.16(VCC) U27.1(VCC) U39.1(VCCI) U39.16(VCCP) U40.1(VCCI) U42.5(VCC) U51.44(IOVDD) U51.45(MFP0) U51.46(MFP1) Y2.4(VCC) Y5.4(VCC)
V5_0D: C2.1 C8.1 C9.1 C131.1 C132.1 J1.2 J5.1 J5.2 J19.1 J19.2 R12.2(P2) R145.2(P2)
